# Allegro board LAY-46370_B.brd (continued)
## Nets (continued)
CSI1_DN2: J1.90 J12.B13 U33.1 U33.10(NC4)
CSI1_DN3: J1.96 J12.B16 U33.4 U33.7
CSI1_DP0: J1.74 J12.B3 U32.2 U32.9
CSI1_DP1: J1.80 J12.B6 U32.5 U32.6
CSI1_DP2: J1.92 J12.B14 U33.2 U33.9
CSI1_DP3: J1.98 J12.B17 U33.5 U33.6
CSI1_I2C_SCL: J12.B11 R162.1
CSI1_I2C_SDA: J12.B10 R160.1
CSI1_SYNC: J1.21 R28.1
CSI2_CKN: J2.16 J13.A2 U34.1 U34.10(NC4)
CSI2_CKP: J2.18 J13.A3 U34.2 U34.9
CSI2_DN0: J2.28 J13.B2 U35.1 U35.10(NC4)
CSI2_DN1: J2.22 J13.B5 U35.4 U35.7
CSI2_DN2: J2.10 J13.B13 U36.1 U36.10(NC4)
CSI2_DN3: J2.4 J13.B16 U36.4 U36.7
CSI2_DP0: J2.30 J13.B3 U35.2 U35.9
CSI2_DP1: J2.24 J13.B6 U35.5 U35.6
CSI2_DP2: J2.12 J13.B14 U36.2 U36.9
CSI2_DP3: J2.6 J13.B17 U36.5 U36.6
CSI2_I2C_SCL: J13.B11 R164.1
CSI2_I2C_SDA: J13.B10 R161.1
CSI2_MCLK: J13.B8 R26.1
CSI2_NRST: J13.B9 R303.1
CSI2_SYNC: J1.32 R25.1 R163.1
CSI_MCLK: J1.12 J12.B8 R26.2
CSI_NRST: J1.19 J12.B9 R303.2
CSI_PWDN: J2.71 J12.A11 R165.1
CSI_SYNC1: J12.A10 R28.2 R29.1
CSI_SYNC2: J13.A10 R25.2 R29.2
DCDC_5V: C16.1 C17.1 C41.1 C42.1 C61.2 C157.1 C256.2 C257.1 C258.1 C259.1 C260.1 C264.1 C270.1 C271.1 J25.1 J25.3 J25.5 J26.1 L16.2 Q8.1 Q8.2 Q8.3(S3) R254.1 R261.1 R267.1 R309.1 R310.1 TP67.1(PIN1) U14.D2 U14.D3 U14.E2 U14.E3 U14.F2 U14.F3 U14.G2 U14.G3 U22.A1 U22.A2(VIN2) U63.5(VOUT) U64.8 U64.11(VIN2) U71.3
DCDC_5V_CN: C158.1 C170.1 C171.1 R1.1 R179.1 R180.1 R185.2 TP125.1(TP) U48.8(VCCB) U71.2(OUT)
DEBUG_ACCESS: TP18.1(PIN1) U11.9
DEBUG_ACCESS1: TP27.1(PIN1) U17.9
DSI_BL_PWM: J1.23 R305.2
DSI_CKN: J1.83 J14.A2 U38.1 U38.10(NC4)
DSI_CKP: J1.85 J14.A3 U38.2 U38.9
DSI_DN0: J1.71 J14.B2 U37.1 U37.10(NC4)
DSI_DN1: J1.77 J14.B5 U37.4 U37.7
DSI_DN2: J1.89 J14.B13 U39.1 U39.10(NC4)
DSI_DN3: J1.95 J14.B16 U39.4 U39.7
DSI_DP0: J1.73 J14.B3 U37.2 U37.9
DSI_DP1: J1.79 J14.B6 U37.5 U37.6
DSI_DP2: J1.91 J14.B14 U39.2 U39.9
DSI_DP3: J1.97 J14.B17 U39.5 U39.6
DSI_EN: J1.30 J14.A11
DSI_NINT: J14.B9 R304.1
DSI_PWM: J14.B8 R305.1
DSI_TS_NINT: J1.28 R304.2
DSI_TS_SCL: J14.B11 R167.1
DSI_TS_SDA: J14.B10 R166.1
EARC_N_HPD: C162.1 J4.53 TP88.1(PIN1)
EARC_P_UTIL: C161.1 J4.55 TP87.1(PIN1)
ECSPI2_MISO: J4.37 U55.4
ECSPI2_MISO_3V3: J21.21 U55.8
ECSPI2_MOSI: J4.35 U55.3
ECSPI2_MOSI_3V3: J21.19 U55.9
ECSPI2_SCLK: J4.31 U55.5
ECSPI2_SCLK_3V3: J21.23 U55.7
ECSPI2_SS0: J4.33 U55.2
ECSPI2_SS0_3V3: J21.24 U55.10
EN_SNK1: Q2.3 R64.2 R65.1 U14.F1
EN_SRC1: R55.2 U14.G1
ENET1_EVENT_IN: R317.2 TP42.1(TP)
ENET1_EVENT_OUT: R318.2 TP56.1(TP)
ENET1_MDC: J3.86 R110.2
ENET1_MDIO: J3.88 R100.1 R111.2
ENET1_NINT: R114.1 U4.12 U26.31
ENET1_NRST: R113.1 U4.14 U26.12
ENET1_RD0: J3.92 R105.2
ENET1_RD1: J3.94 R103.2
ENET1_RD2: J3.96 R102.2
ENET1_RD3: J3.98 R106.2
ENET1_RX_CTL: J3.95 R107.2
ENET1_RXC: C99.1 J3.73 R108.2
ENET1_RXC/PHYAD1: R108.1 R119.1 R439.2 U26.27
ENET1_RXCTL/PHYAD2: R107.1 R126.1 U26.26
ENET1_RXD0/RXDLY: R105.1 R118.2 R125.1 U26.25
ENET1_RXD1/TXDLY: R103.1 R117.2 R124.1 U26.24
ENET1_RXD2/PLLOFF: R102.1 R120.2 R128.1 U26.23
ENET1_RXD3/PHYAD0: R106.1 R127.2 R438.1 U26.22
ENET1_TD0: J3.75 U26.18
ENET1_TD1: J3.77 U26.17
ENET1_TD2: J3.81 U26.16
ENET1_TD3: J3.83 U26.15
ENET1_TX_CTL: J3.85 U26.19
ENET1_TXC: J3.87 U26.20
ENET_MDC: J4.52 R79.2 R424.2
ENET_MDIO: J4.54 R80.2 R85.1 R425.2
ENET_NINT: R84.1 U4.13 U23.31
ENET_NRST: R83.1 U4.15 U23.12
ENET_RD0: J4.82 R73.2
ENET_RD1: J4.84 R72.2
ENET_RD2: J4.86 R71.2
ENET_RD3: J4.88 R75.2
ENET_RX_CTL: J4.72 R76.2
ENET_RXC: C81.1 J4.74 R77.2
ENET_TD0: J4.62 U23.18
ENET_TD1: J4.64 U23.17
ENET_TD2: J4.66 U23.16
ENET_TD3: J4.68 U23.15
ENET_TX_CTL: J4.56 U23.19
ENET_TXC: J4.58 U23.20
ETH1_1GB_LINK/ACTIVE: J9.11 R109.1
ETH1_10M_100M_LINK/ACTIVE: J9.13 R104.1
ETH1_AVDD1V0: C84.1 C85.1 C86.1 C339.1 L7.2 U26.3 U26.8 U26.38
ETH1_AVDD3V3: C87.1 C88.1 L6.2 U26.11 U26.40
ETH1_CLK125_OUT: TP35.1(PIN1) U26.35
ETH1_DVDD1V0: C14.1 C93.1 L8.2 U26.21
ETH1_DVDD3V3: C89.1 C90.1 L5.2 R115.1 R116.1 U26.29
ETH1_LED0/CFG_EXT: R115.2 R121.1 U26.32
ETH1_LED1/CFGLDO0: C100.1 J9.14 R123.1 U26.33
ETH1_LED2/CFGLDO1: C101.1 J9.12 R116.2 R122.1 U26.34
ETH1_MDC: R110.1 R424.1 U26.13
ETH1_MDIO: R111.1 R425.1 U26.14
ETH1_TRX0_N: J9.3 U26.2 U28.2 U28.9
ETH1_TRX0_P: J9.2 U26.1 U28.1 U28.10(NC4)
ETH1_TRX1_N: J9.5 U26.5 U28.5 U28.6
ETH1_TRX1_P: J9.4 U26.4 U28.4 U28.7
ETH1_TRX2_N: J9.7 U26.7 U27.2 U27.9
ETH1_TRX2_P: J9.6 U26.6 U27.1 U27.10(NC4)
ETH1_TRX3_N: J9.9(TRD4-) U26.10 U27.5 U27.6
ETH1_TRX3_P: J9.8 U26.9 U27.4 U27.7
ETH1_VDD1V0: C95.1 C96.1 L7.1 L8.1 U26.30
ETH1_VDDIO: C91.1 C92.1 R100.2 R101.2 R117.1 R118.1 R120.1 R127.1 R439.1 TP34.1(TP) U26.28
ETH1_XTALI: C97.1 U26.36 Y2.1
ETH1_XTALO: C98.1 U26.37(XTAL_OUT/ EXT_CLK) Y2.3
ETH_AVDD1V0: C65.1 C66.1 C67.1 C333.1 L3.2 U23.3 U23.8 U23.38
ETH_AVDD3V3: C68.1 C69.1 L2.2 U23.11 U23.40
ETH_CLK125_OUT: TP33.1(PIN1) U23.35
ETH_CT: C75.1 J8.1
ETH_CT1: C94.1 J9.1
ETH_DVDD1V0: C74.1 C334.1 L4.2 U23.21
ETH_DVDD3V3: C70.1 C71.1 L1.2 R86.1 R87.1 U23.29
ETH_TRX0_N: J8.3 U23.2 U25.2 U25.9
ETH_TRX0_P: J8.2 U23.1 U25.1 U25.10(NC4)
ETH_TRX1_N: J8.5 U23.5 U25.5 U25.6
ETH_TRX1_P: J8.4 U23.4 U25.4 U25.7
ETH_TRX2_N: J8.7 U23.7 U24.2 U24.9
ETH_TRX2_P: J8.6 U23.6 U24.1 U24.10(NC4)
ETH_TRX3_N: J8.9(TRD4-) U23.10 U24.5 U24.6
ETH_TRX3_P: J8.8 U23.9 U24.4 U24.7
ETH_VDD1V0: C76.1 C77.1 L3.1 L4.1 U23.30
ETH_VDDIO: C72.1 C73.1 R70.2 R85.2 R88.1 R89.1 R90.1 R91.1 TP32.1(TP) U23.28
ETH_XTALI: C79.1 U23.36 Y1.1
ETH_XTALO: C80.1 U23.37(XTAL_OUT/ EXT_CLK) Y1.3
EX_POR_B: R407.2 U1.24 U2.4(Y)
EXP_P0_7: J21.22 R142.2 U1.8
EXP_P1_0: J21.12 U1.10
EXP_P1_1: J21.13 U1.11
EXP_P1_2: J21.15 U1.12
EXP_P1_3: J21.16 U1.13
EXP_P1_4: J21.18(B9) U1.14
EXP_P1_5: J21.29 U1.15
EXP_P1_6: J21.31 U1.16
EXP_P1_7: J21.33 U1.17
EXT_3V3_PG: TP71.1(TP) U64.7
EXT_PWREN1: R271.1 U1.1
EXT_PWREN2: R281.1 R450.1 U1.2
FAN_5V: C348.1 J27.1 Q16.3
FAN_EN: R456.1 U1.5
FRS_EN: TP97.1(PIN1) U11.1
FRS_EN1: U14.B6 U17.1
FT_BOOT_MODE0: R386.2 U20.1
FT_BOOT_MODE1: R387.2 U20.4
FT_BOOT_MODE2: R388.2 U20.8
FT_BOOT_MODE3: R389.2 U20.11
FT_EECS: R240.2 U60.63
FT_EEDATA: R236.2 U60.61
FT_GPIO1: J25.25 U60.30
FT_GPIO2: J25.27 U60.32
FT_GPIO3: J25.31 U60.33
FT_GPIO4: J25.33 U60.34
FT_IO_01: J25.14 R390.2
FT_IO_02: J25.16 R391.2
FT_IO_03: J25.18 R392.2
FT_IO_04: J25.22 R393.2
FT_IO_05: J25.24 R395.2
FT_IO_06: J25.26 R396.2
FT_IO_07: J25.28 R397.2
FT_IO_08: J25.32 R398.2
FT_IO_09: J25.34 R399.2
FT_IO_10: J25.36 R400.2
FT_IO_11: J25.38 R401.2
FT_IO_NINT: R449.1 U60.29
FT_IO_NRST: J25.37 R412.1 U60.23
FT_IOEXP_SCL: R363.2 U70.19
FT_IOEXP_SDA: R364.2 U70.20
FT_ONOFF_B: R382.1 U60.24
FT_OSCI: C252.1 U60.2 X1.1
FT_OSCO: C253.1 U60.3 X1.3
FT_PWREN: TP93.1(PIN1) U60.60
FT_REMOTE_SEL: R394.2 R409.2 TP134.1(PIN1) U67.2
FT_RESET_B: J25.35 U60.21
FT_SCL: J25.21 R333.2 R363.1 R441.1 TP130.1(TP) U60.26
FT_SDA: J25.23 R334.2 R364.1 R442.1 TP129.1(TP) U60.27 U60.28
FT_SUSPEND_B: R408.1 TP96.1(PIN1) U60.36
FT_SYS_NRST: TP133.1(PIN1) U60.22 U66.2
FT_USB_DN: R327.1 U62.C2
FT_USB_DP: R328.1 U62.C1
FTA_TCK: U7.2 U60.16
FTA_TDI: U7.3 U60.17
FTA_TDO: U7.5 U60.18
FTA_TMS: U7.4 U60.19
FTDIC_RX: D17.C(CATHODE) U60.39 U61.15
FTDIC_TX: D16.C(CATHODE) U60.38 U61.13
FTDID_RX: D21.C(CATHODE) U60.52 U61.14
FTDID_TX: D20.C(CATHODE) U60.48 U61.12
GPIO1_IO00: J1.25 R315.1
GPIO1_IO12: J1.20 R308.1
HDMI_5V_CN: D10.1 J17.18 R1.2
HDMI_CEC: D32.A J4.49 Q5.2(SOURCE) R186.2
HDMI_CEC_CN: D13.1 D32.C(CATHODE) J17.13 Q5.3 R174.2
HDMI_CLKN_CN: J17.12 U46.A4
HDMI_CLKP_CN: J17.10 U46.A3
HDMI_DDC_SCL: J4.41 R177.2 R181.1 TP89.1(TP)
HDMI_DDC_SCL_CN: D12.1 J17.15 R179.2 U48.7
HDMI_DDC_SDA: J4.43 R178.2 R183.1 TP90.1(TP)
HDMI_DDC_SDA_CN: D11.1 J17.16 R180.2 U48.6
HDMI_HPD: J4.47 U79.4(Y)
HDMI_HPD/EARC-: C162.2 R175.2 TP95.1(PIN1) U30.C2
HDMI_HPD_5V: R175.1 R176.1 U79.2
HDMI_HPD_CN: J17.19 U30.A2
HDMI_TXCN: J4.59 U46.C4
HDMI_TXCP: J4.61 U46.C3
HDMI_TXN0: J4.65 U46.C2
HDMI_TXN0_CN: J17.9 U46.A2
HDMI_TXN1: J4.71 U47.C4
HDMI_TXN1_CN: J17.6 U47.A4
HDMI_TXN2: J4.77 U47.C2
HDMI_TXN2_CN: J17.3 U47.A2
HDMI_TXP0: J4.67 U46.C1
HDMI_TXP0_CN: J17.7 U46.A1
HDMI_TXP1: J4.73 U47.C3
HDMI_TXP1_CN: J17.4 U47.A3
HDMI_TXP2: J4.79 U47.C1
HDMI_TXP2_CN: J17.1 U47.A1
HDMI_UTILITY/EARC+: C161.2 TP94.1(PIN1) U30.C1
HDMI_UTILITY_CN: J17.14(UTILITY) U30.A1
HP_J_D: J18.5 R187.2 R189.2 TVS5.2(A2)
HP_J_L: C176.2 J18.4 L11.2 TVS4.2(A2)
HP_J_MIC: C193.1 J18.1 L13.2 TVS3.2(A2)
HP_J_R: C179.1 J18.3 L12.2 TVS6.2(A2)
HP_JD: R189.1 U50.7
HP_L: C177.1 U50.31
HP_MIC1N: C181.2 C183.1 U50.4
HP_MIC1P: C191.1 C192.1 U50.2
HP_MIC_P: C191.2 L13.1 R201.2
HP_R: C178.1 U50.29
HPL: C177.2 L11.1 R190.2
HPR: C178.2 L12.1 R196.1
I2C2_SCL: J3.55 R7.2 R153.2 R162.2 R167.2 R172.2 TP5.1(TP) U5.2
I2C2_SCL_3V3: R11.2 R58.1 R61.1 R133.1 U5.10
I2C2_SDA: J3.57 R8.2 R152.2 R160.2 R166.2 R170.2 TP6.1(TP) U5.3
I2C2_SDA_3V3: R12.2 R59.1 R62.1 R134.1 U5.9
I2C3_SCL: J3.61 R9.2 R164.2 R173.2 R198.1 R306.1 TP7.1(TP) U5.4
I2C3_SCL_3V3: J21.5 R13.2 R291.1 U5.8
I2C3_SDA: J3.63 R10.2 R161.2 R171.2 R197.1 R307.1 TP8.1(TP) U5.5
I2C3_SDA_3V3: J21.3 R14.2 R292.1 U5.7
I2C4_SCL: J3.65 R16.2 U6.2
I2C4_SDA: J3.67 R17.2 U6.3
I2C5_SCL: R18.2 TP9.1(TP) U6.4 U52.11
I2C5_SCL_3V3: R22.2 R221.1 U6.8
I2C5_SDA: R19.2 TP10.1(TP) U6.5 U52.8
I2C5_SDA_3V3: R23.2 R222.1 U6.7
ILIM_5V_VBUS: TP20.1(PIN1) U11.6
ILIM_5V_VBUS1: TP29.1(PIN1) U17.6
IOEXP_NINT: R308.2 U1.22
IOEXP_SCL: R306.2 U1.19
IOEXP_SDA: R307.2 U1.20
JTAG_MOD: J1.66 R313.1 TP122.1(PIN1)
JTAG_RESET: D23.C D26.C J24.10(B5) R245.2
JTAG_TCK: J1.68 U8.2
JTAG_TDI: J1.64 U8.5
JTAG_TDO: J1.62 U8.10
JTAG_TMS: J1.60 U8.7
LD1_I2C_SCL: R61.2 U14.B1
LD1_I2C_SDA: R62.2 U14.C1
LD1_NINT: R60.2 R63.2 U14.D1
LED0/CFG_EXT: R86.2 R92.1 U23.32
LED1/CFGLDO0: C82.1 J8.14 R94.1 U23.33
LED2/CFGLDO1: C83.1 J8.12 R87.2 R93.1 U23.34
LVDS0_CLK_N: J2.47 J15.A2 U40.1 U40.10(NC4)
LVDS0_CLK_P: J2.45 J15.A3 U40.2 U40.9
LVDS0_TS_SCL: J15.B11 R172.1
LVDS0_TS_SDA: J15.B10 R170.1
LVDS0_TX0_N: J2.35 J15.B2 U41.1 U41.10(NC4)
LVDS0_TX0_P: J2.33 J15.B3 U41.2 U41.9
LVDS0_TX1_N: J2.41 J15.B5 U41.4 U41.7
LVDS0_TX1_P: J2.39 J15.B6 U41.5 U41.6
LVDS0_TX2_N: J2.53 J15.B13 U42.1 U42.10(NC4)
LVDS0_TX2_P: J2.51 J15.B14 U42.2 U42.9
LVDS0_TX3_N: J2.59 J15.B16 U42.4 U42.7
LVDS0_TX3_P: J2.57 J15.B17 U42.5 U42.6
LVDS1_CLK_N: J2.17 J16.A2 U43.1 U43.10(NC4)
LVDS1_CLK_P: J2.15 J16.A3 U43.2 U43.9
LVDS1_TS_SCL: J16.B11 R173.1
LVDS1_TS_SDA: J16.B10 R171.1
LVDS1_TX0_N: J2.5 J16.B2 U44.1 U44.10(NC4)
LVDS1_TX0_P: J2.3 J16.B3 U44.2 U44.9
LVDS1_TX1_N: J2.11 J16.B5 U44.4 U44.7
LVDS1_TX1_P: J2.9 J16.B6 U44.5 U44.6
LVDS1_TX2_N: J2.23 J16.B13 U45.1 U45.10(NC4)
LVDS1_TX2_P: J2.21 J16.B14 U45.2 U45.9
LVDS1_TX3_N: J2.29 J16.B16 U45.4 U45.7
LVDS1_TX3_P: J2.27 J16.B17 U45.5 U45.6
LVDS_BL_PWM: J1.22 J15.B8 R168.2
LVDS_EN: J1.26 J15.A11 J16.A11
LVDS_TS_NINT: J1.18 J15.B9 R169.2
LVL_SHF_TCK: U7.10 U8.1
LVL_SHF_TDI: U7.9 U8.4
LVL_SHF_TDO: U7.7 U8.11
LVL_SHF_TMS: U7.8(YB3) U8.8
M2_BT_WAKE: D6.C J10.20 R149.2
M2_BT_WAKE_HOST: D6.A J2.95
M2_DIS1: J10.56 R32.1
M2_DIS2: J10.54(W\_\D\I\S\A\B\L\E\2\) R142.1 TP39.1(PIN1)
M2_I2C_SCL: J10.60 R153.1
M2_I2C_SDA: J10.58 R152.1
M2_LED1#: D30.C(CATHODE) J10.6
M2_LED2#: D31.C(CATHODE) J10.16
M2_PCM_CLK: J4.11 J10.8
M2_PCM_IN: J4.17 J10.12
M2_PCM_OUT: J4.15 J10.14
M2_PCM_SYNC: J4.13 J10.10
M2_PERST: J10.52 R31.1
M2_SD_CLK: J2.75 J10.9
M2_SD_CMD: J2.77 J10.11
M2_SD_DATA0: J2.81 J10.13
M2_SD_DATA1: J2.83 J10.15
M2_SD_DATA2: J2.85 J10.17
M2_SD_DATA3: J2.87 J10.19
M2_SD_NRST: J2.73 J10.23
M2_SD_WAKE_HOST: J2.97 J10.21
M2_UART_CTS: J3.56 R372.2 TP119.1(TP)
M2_UART_RTS: J3.58 R371.2 TP118.1(TP)
M2_UART_RXD: J3.54 R369.2 TP116.1(TP)
M2_UART_TXD: J3.52 R370.2 TP117.1(TP)
M2_USB_DN: J10.5 R301.2 TP38.1(PIN1)
M2_USB_DP: J10.3 R300.2 TP37.1(PIN1)
MICBIAS: C174.1 R199.1 U50.1
NAND_DQS: J2.72 U3.8
NX5P_EN: R302.2 U22.B4
NX5P_FLT#: R448.2 U22.A4
NX5P_FRS: R68.2 U22.C4
NX5P_ILIM: R67.2 U22.A3
NX20P_ACK: R43.1 TP13.1(PIN1) U9.A2
NX20P_EN: C164.1 Q1.3 R42.2 U9.A3(\\E\N)
NX20P_OVLO: R44.1 U9.B3
ONOFF: J2.74 R381.2 SW1.3 SW1.4(B2) TP120.1(PIN1)
P0_0: R386.1 U70.1
P0_1: R387.1 U70.2
P0_2: R388.1 U70.3
P0_3: R389.1 U70.4
P0_4: R390.1 U70.5
P0_5: R391.1 U70.6
P0_6: R392.1 U70.7
P0_7: R393.1 U70.8
P1_0: R394.1 U70.10
P1_1: R395.1 R415.2 U70.11
P1_2: R396.1 R416.2 U70.12
P1_3: R397.1 R417.2 U70.13
P1_4: R398.1 R418.2 U70.14
P1_5: R399.1 R419.2 U70.15
P1_6: R400.1 R420.2 U70.16
P1_7: R401.1 R421.2 U70.17
PCIE_CLKN: J1.53 R132.2 R136.1
PCIE_CLKP: J1.55 R131.2 R135.1
PCIE_DIG1: C102.1 C103.1 C349.1 R129.2 R130.2 U29.7 U81.6
PCIE_NCLKREQ_3V3: J10.53 R20.2 R144.1 TP98.1(PIN1) U6.10 U81.2
PCIE_NDIS_3V3: R32.2 R33.1 TP101.1(TP) U3.21
PCIE_NRST_3V3: R31.2 TP100.1(TP) U3.20
PCIE_NWAKE_3V3: J10.55 R21.2 U6.9
PCIE_REQ: R139.1 R140.1 R144.2 U81.4(Y)
PCIE_RXN: J1.59 J10.43
PCIE_RXP: J1.61 J10.41
PCIE_TXN: C121.1 J1.65
PCIE_TXP: C120.1 J1.67
PD1_I2C_SCL: R58.2 U17.8
PD1_I2C_SDA: R59.2 U17.7
PD_EN_SNK: Q2.1 R2.1 U11.2
PD_EN_SNK1: R64.1 U17.2
PD_EN_SRC: TP17.1(PIN1) U11.16
PD_EN_SRC1: R55.1 U17.16
PD_I2C_SCL: R291.2 U11.8
PD_I2C_SDA: R292.2 U11.7
PDM/CAN2_SEL: R445.1 U1.4 U54.10
PDM_CLK: J21.40 U58.10
PDM_STREAM_0: J21.38 U57.10
PDM_STREAM_1: J21.37 U57.9
PDM_STREAM_2: J21.36 U57.8
PDM_STREAM_3: J21.35 U57.7
PER_12V: C146.1 C151.1 C280.1 C281.1 C282.1 J15.A8 J15.A9 J16.A8 J16.A9 L18.2 R276.1 TP105.1(PIN1)
PER_12V_PG: R282.2 TP81.1(TP) U49.6
PMIC_32K_OUT: J3.41 R314.1
PMIC_ON_REQ: J2.78 R265.1
PMIC_SCLH: J3.51 TP54.1(PIN1)
PMIC_SCLL: J3.45 TP52.1(PIN1)
PMIC_SDAH: J3.53 TP55.1(PIN1)
PMIC_SDAL: J3.47 TP53.1(PIN1)
POR_B: D26.A J2.76 R238.1 R407.1 U2.2
POR_B_INVERT: R431.2 R435.1 U78.4(Y)
PWM4_3V3: J21.32 U58.7
PWR_MEAS_IO1: J25.15 U1.6
PWR_MEAS_IO2: J25.17 U1.7
REF_CLK_32K: R314.2 R315.2 U3.5
REF_CLK_32K_3V3: R30.2 U3.19
REF_CLKN_CN: J10.49 R136.2 R138.2
REF_CLKP_CN: J10.47 R135.2 R137.2
REG_FT_1V8: C294.1 C295.1 L24.2 U60.49(VREGOUT)
REMOTE_SEL: Q12.1 R39.2 R351.1 R458.1 U8.15 U20.15
REMOTE_SEL_B: Q12.3 R385.2 U7.12
RXC/PHYAD1: R77.1 R98.1 U23.27
RXCTL/PHYAD2: R76.1 R97.1 U23.26
RXD0/RXDLY: R73.1 R89.2 R96.1 U23.25
RXD1/TXDLY: R72.1 R88.2 R95.1 U23.24
RXD2/PLLOFF: R71.1 U23.23
RXD2_PLLOFF: R91.2 R99.1
RXD3/PHYAD0: R75.1 R90.2 U23.22
S_TXN1: C48.2 U18.7
S_TXN2: C53.2 U18.6
S_TXP1: C50.2 U18.8
S_TXP2: C52.2 U18.5
SAI1_RXC: J3.78 R318.1
SAI1_RXD0: J3.82 U4.7
SAI1_RXD1: J3.84 U4.9
SAI1_RXFS: J3.76 R317.1
SAI2_MCLK: J4.18 U3.10
SAI2_RXC: J4.14 U4.6
SAI2_RXFS: J4.12 U4.8
SAI3_MCLK: J4.22 R195.1
SAI3_RXD: J4.28 R194.1
SAI3_TXC: J4.21 R191.1
SAI3_TXD: J4.25 R193.1
SAI3_TXFS: J4.23 R192.1
SAI5_RX3: J4.7 U54.1
SAI5_RXC: J4.4 R297.1 TP86.1(TP)
SAI5_RXD0: J4.1 R293.1 TP82.1(TP)
SAI5_RXD1: J4.3 R294.1 TP83.1(TP)
SAI5_RXD2: J4.5 R295.1 TP84.1(TP)
SAI5_RXD3: R296.1 TP85.1(TP) U54.2
SAI5_RXFS: J4.2 U58.5
SD1_DATA4: J2.91 U3.3
SD1_DATA5: J2.93 R41.2 U3.4
SD2_CLK: J4.96 R155.1
SD2_CMD: J4.98 R154.1
SD2_DATA0: J4.91 R156.1
SD2_DATA1: J4.93 R157.1
SD2_DATA2: J4.95 R158.1
SD2_DATA3: J4.97 R159.1
SD2_NCD: J4.94 J11.9 TP40.1(PIN1) TVS1.2(A2)
SD2_RESET_B: J4.87 TP62.1(PIN1)
SPDIF_EXT_CLK: J4.36 U3.9
SPDIF_RX: J4.34 TP12.1(TP) U52.4
SPDIF_TX: J4.32 TP11.1(TP) U52.1
SPK_LN: R208.1 U50.23
SPK_LP: R206.1 U50.25
SPK_RN: R203.1 U50.19
SPK_RP: R202.1 U50.22
SPKOUTLN: C199.2 C201.1 CON1.4 R208.2
SPKOUTLP: C198.2 C199.1 CON1.3 R206.2
SPKOUTRN: C195.2 C196.1 CON1.2 R203.2
SPKOUTRP: C194.2 C195.1 CON1.1 R202.2
SS_RXN1: U18.1 U19.C2
SS_RXN2: U18.16 U19.C4
SS_RXP1: U18.2 U19.C1
SS_RXP2: U18.15 U19.C3
SS_TXN1: C48.1 U16.C3
SS_TXN2: C53.1 U16.C1
SS_TXP1: C50.1 U16.C4
SS_TXP2: C52.1 U16.C2
SSRXN1: J6.B10 U19.A2
SSRXN2: J6.A10 U19.A4
SSRXP1: J6.B11 U19.A1
SSRXP2: J6.A11 U19.A3
SSTXN1: J6.A3 U16.A3
SSTXN2: J6.B3 U16.A1
SSTXP1: J6.A2 U16.A4
SSTXP2: J6.B2 U16.A2
ST_FT_USB_DN: R327.2 U60.7
ST_FT_USB_DP: R328.2 U60.8
SUSCLK_3V3: J10.50 R30.1 TP99.1(TP)
SW_BOOT_MODE0: R287.1 SW4.4 U20.16
SW_BOOT_MODE1: R288.1 SW4.3 U20.3
SW_BOOT_MODE2: R289.1 SW4.2 U20.9
SW_BOOT_MODE3: R290.1 SW4.1 U20.12
SYS_NRST: D23.A J3.43 R406.2 R436.2 TP121.1(PIN1)
TCPC_NINT: J3.91 TP22.1(TP) U11.10
TCPC_NINT1: J3.93 TP31.1(TP) U17.10
TYPEC_EN_B: R40.1 U18.3(XSD)
UART2_RXD: J3.64 R232.1 TP58.1(TP)
UART2_TXD: J3.62 R230.1 TP57.1(TP)
UART3_CTS: J4.42 U56.4
UART3_CTS_3V3: J21.7 U56.8
UART3_RTS: J4.44 U56.5
UART3_RTS_3V3: J21.11 U56.7
UART3_RXD: J4.48 U56.3
UART3_RXD_3V3: J21.10 U56.9
UART3_TXD: J4.46 U56.2
UART3_TXD_3V3: J21.8 U56.10
UART4_RXD: J3.68 R233.1 TP61.1(TP)
UART4_TXD: J3.66 R231.1 TP60.1(TP)
USB1_CC1: TP28.1(PIN1) U15.A2 U17.13
USB1_CC1_CN: J6.A5 U15.A1
USB1_CC2: TP30.1(PIN1) U15.B2 U15.C1 U15.C2 U17.14
USB1_CC2_CN: J6.B5 U15.B1
USB1_DN: J1.36 U75.C1
USB1_DN_CN: J6.A7 J6.B7 U75.A1
USB1_DNU(USB1_ID): TP45.1(PIN1)
USB1_DP: J1.38 U75.C2
USB1_DP_CN: J6.A6 J6.B6 U75.A2
USB1_OTG_VBUS: F2.1 J6.A4 J6.A9 J6.B4(VBUS4) J6.B9
USB1_OTG_VBUS_F: C36.1 D4.A F2.2 R5.1 R47.1 U14.C2 U14.C3 U14.C4 U14.C5 U14.D4 U14.D5 U14.E4 U14.E5 U14.F4 U14.F5 U14.G4 U14.G5 U17.15
USB1_RXN: J1.29 U18.14
USB1_RXP: J1.31 U18.13
USB1_SBU1: J6.A8 TP24.1(PIN1)
USB1_SBU2: J6.B8 TP25.1(PIN1)
USB1_SS_SEL: J3.97 R38.1 U18.12
USB1_TXN: J1.35 U18.9
USB1_TXP: J1.37 U18.10
USB1_TYPEC_EN_B: J4.92 R40.2
USB1_VBUS_3V3: J1.44 R48.2 U12.1
USB1_VBUS_IN: C43.2 R53.1 R54.1 TP110.1(PIN1) U14.C6 U14.D6 U14.E6 U14.F6 U14.G6
USB2_DN: J1.54 R299.2 R301.1
USB2_DNU(USB2_ID): TP46.1(PIN1)
USB2_DP: J1.56 R298.2 R300.1
USB2_H_DN: R299.1 U77.C1
USB2_H_DP: R298.1 U77.C2
USB2_H_TXN: C60.1 U21.C2
USB2_H_TXP: C59.1 U21.C1
USB2_HOST_VBUS: C62.1 D5.C J7.1(VBUS) TP103.1(TP) U22.C2 U22.D1 U22.D2
USB2_PWR_EN: J1.16 R302.1
USB2_RXN: J1.41 U21.C4
USB2_RXP: J1.43 U21.C3
USB2_TXN: C60.2 J1.47
USB2_TXP: C59.2 J1.49
USB2_VBUS_3V3: J1.50 R66.2
USB_CC1: TP19.1(PIN1) U10.A2 U11.13
USB_CC1_CN: J5.A5 SW3.3
USB_CC1_ESD: SW3.2 U10.A1
USB_CC2: TP21.1(PIN1) U10.B2 U10.C1 U10.C2 U11.14
USB_CC2_CN: J5.B5 SW3.6(NO2)
USB_CC2_ESD: SW3.5 U10.B1
USB_DBG_DN: J23.2 U62.A2
USB_DBG_DP: J23.3 U62.A1
USB_HOST_DN: J7.2 U77.A1
USB_HOST_DP: J7.3 U77.A2
USB_HOST_RXN: J7.5 U21.A4
USB_HOST_RXP: J7.6 U21.A3
USB_HOST_TXN: J7.8 U21.A2
USB_HOST_TXP: J7.9 U21.A1
USB_LD_NFLT: R447.1 U11.11
USB_LD_NFLT1: R63.1 U17.11
USB_PWR_VBUS_F: C24.1 D2.A F1.2 R42.1 R453.1 U9.B2 U9.C2 U9.D2 U9.E1 U9.E2 U11.15
USB_SBU1: J5.A8 TP14.1(PIN1)
USB_SBU2: J5.B8 TP15.1(PIN1)
VEXP_3V3: C224.1 C229.1 C231.1 C233.1 C235.1 J21.1 J21.17 L25.2 U55.11(VCCB) U56.11(VCCB) U57.11(VCCB) U58.11(VCCB)
VEXP_5V: C226.1 J21.2 J21.4 L26.2
VEXT_3V3: C127.1 C128.1 C133.1 C134.1 C139.1 C140.1 C144.1 C149.1 C153.1 C155.1 C223.2 C272.1 C273.1 C274.1 C275.1 C276.2 C340.1 C342.1 J12.A13 J12.A14 J13.A13 J13.A14 J14.A13 J14.A14 J15.A13 J15.A14 J16.A13 J16.A14 J22.1 J22.2 L17.2 L25.1 Q14.1 Q14.2 Q14.3(S3) R36.1 R268.1 R451.1 TP70.1(PIN1) U64.2
VEXT_3V3_EN: R37.1 U3.16
VLDO1_3V3: C47.1 U14.A5(VLDO)
VLDO_3V3: C27.1 C35.1 C45.1 C46.1 TP23.1(TP) U10.A3(VSYS) U13.5(OUT) U14.A1 U15.A3(VSYS)
VPCIE_3V3: C112.1 C113.1 C114.1 C115.1 C116.1 C117.1 C118.1 C119.1 C341.2 J10.2 J10.4 J10.72 J10.74 Q14.5 R35.1 R149.1 R373.2 R374.2 TP104.1(TP)
VSD_3V3: C123.1 C124.1 J3.42 J3.44 J3.46 J11.4 TP41.1(PIN1) TVS2.2(A2)
VSYS_5V: J3.1 J3.2 J3.3 J3.4 J3.5 J3.6 J3.7 J3.8 J3.9 J3.10 J3.11 J3.12 J26.2 R309.2 R310.2
VTREF: J24.1 R246.2
WDOG_B: J1.10 R437.2
N98831920: J11.5 R155.2
N101118683: J11.8 R157.2
N101118691: J11.7 R156.2
N101118780: J11.3 R154.2
N101118796: J11.1 R158.2
N101783582: J11.2 R159.2
N101995244: C107.1 C108.1 C109.1 L10.2 U29.11 U29.20
N101995252: C111.1 U29.2(X2) Y3.3
N101995256: C110.1 U29.1 Y3.1
N101995353: C104.1 C105.1 C106.1 L9.1 U29.3 U29.16
N101995404: R131.1 U29.13
N101995406: TP36.1(PIN1) U29.4
N101995408: R132.1 U29.14
N101995436: R137.1 U29.17
N101995453: R138.1 U29.18
N101995643: R140.2 U29.19
N101995645: R139.2 U29.12
N101995688: R141.2 U29.23
N103620610: C265.1 D24.C(CATHODE) R24.1 R252.2 TVS8.2(A2)
N103620792: C254.2 L16.1 R253.1 U63.7
N103620806: R251.1 U63.8
N103620818: C254.1 R251.2
N103621273: R254.2 R256.2 R260.1 U63.11
N103621294: R258.2 R259.1 U63.6
N104279466: R133.2 U29.8
N104279469: R134.2 U29.9
N104764716: R147.2 R148.2 U29.5
N105095140: C120.2 J10.35
N105095143: C121.2 J10.37
N106947509: C261.2 C264.2 Q8.4 R261.2 R263.1
N106947511: Q10.3 R263.2
N106947532: C269.1 Q10.1 R264.2 R265.2 R266.1
N107574242: J22.3 J22.4 R221.2
N107574341: J22.5 J22.6 R222.2
N107626870: C277.1 R37.2 R269.2 R271.2 R272.1 U64.5
N107626960: C272.2 R268.2 R273.1 U64.3
N107627021: R267.2 U64.6
N107627023: L17.1 U64.1 U64.9
N107627186: C276.1 U64.4
N107870832: C256.1 R253.2 R256.1
N107900649: R24.2 U63.12
N108223184: C240.1 U59.4
N108629575: J12.A8 J12.A9 TP43.1(PIN1)
N108650969: C43.1 U14.A6
N108650998: C44.1 U14.A3
N108651072: R56.2 U14.A2
N108651079: R57.2 U14.E1
N108651264: TP26.1(PIN1) U15.C3
N108688907: C64.1 U22.D4
N108749685: R188.2 U50.15
N108749687: C175.1 U50.27(VMID)
N108749719: R192.2 U50.13
N108749740: R191.2 U50.12
N108749771: R194.2 U50.16
N108749815: R193.2 U50.14
N108749834: R195.2 U50.11
N108749893: TP51.1(PIN1) U50.30
N108750085: C182.1 R199.2 R200.1
N108750181: C183.2 R200.2 R201.1
N108752359: C197.2 Q6.1 R204.2 R205.1
N108752379: Q7.3 R205.2
N108752409: C200.1 Q7.1 R207.2 R209.1
N108779922: D5.A U22.B1 U22.B2 U22.C1
N108856282: R81.1 U23.39
N108894167: R79.1 U23.13
N108894170: R80.1 U23.14
N108934835: R112.1 U26.39
N108973788: F1.1 J5.A4 J5.A9 J5.B4(VBUS4) J5.B9
N108973950: TP16.1(PIN1) U10.C3
N108990768: R4.2 U3.2
N108992491: R15.2 U5.12
N108999488: C163.1 Q1.1 R2.2 R45.1
N109006824: C278.1 U49.10
N109006844: C278.2 L18.1 U49.9
N109007030: C280.2 R276.2 R280.1 U49.14
N109010135: R281.2 U49.4
N109011918: D25.A R270.2
N109066072: C207.1 R210.2 R211.2
N109088165: C215.1 R214.2 R215.2
N109209998: J13.A8 J13.A9 TP44.1(PIN1)
N109210079: J13.A11 R163.2 R165.2
N109239152: R181.2 U48.2
N109239179: R183.2 U48.3
N109242668: R185.1 U48.5
N109294186: J14.A8 J14.A9 TP47.1(PIN1)
N109296461: J14.A10 TP48.1(PIN1)
N109299410: J15.A10 TP49.1(PIN1)
N109302474: J16.B8 R168.1
N109302491: J16.B9 R169.1
N109302514: J16.A10 TP50.1(PIN1)
N109310681: R218.2 U53.1 U53.16
N109310959: R216.2 U53.4
N109310972: R217.2 U53.5
N109373964: R223.2 U55.12
N109397839: R224.2 U56.12
N109400332: R225.2 U57.12
N109402713: R226.2 U58.12
N109415208: R27.2 U6.12
N109503700: R293.2 U57.2
N109503714: R294.2 U57.3
N109503728: R295.2 U57.4
N109503742: R296.2 U57.5
N109503902: R297.2 U58.2
N109622186: R406.1 SW2.3 SW2.4(B2)
N109731195: R312.2 U4.4
N109731201: R322.2 U4.5
N109731216: R323.2 U4.1 U4.16
N109737134: C241.1 L21.2 U60.9
N109737207: C242.1 L22.2 U60.4
N109737719: C251.1 R329.2 U60.14
N109737725: R330.1 U60.6
N109773309: D20.A R242.1
N109773326: D21.A R241.1
N109773834: D16.A R235.1
N109773857: D17.A R237.1
N109792630: R347.1 U8.13
N109864993: D22.C R245.1
N109865112: J24.7 R247.1
N109865133: J24.9 R248.1
N109916641: R427.1 U20.13
N109928082: J10.34 R371.1
N109928083: J10.32 R370.1
N109928084: J10.36 R372.1
N109928085: J10.22 R369.1
N109928213: D30.A R373.1
N109928444: D31.A R374.1
N109980953: Q11.1 R382.2 R383.2
N109981204: Q11.3 R381.1
N109995760: C325.1 L23.1 U74.5(VOUT)
N109995782: C326.1 U74.4
N110028547: R408.2 R410.2 U67.1
N110029062: R39.1 U67.4(Y)
N110030307: R411.2 R412.2 U70.24
N110030899: R413.2 R449.2 U70.22
N110063389: J10.38 R422.1
N110063392: J10.40 R423.1
N110097895: C34.1 D2.C(CATHODE) D4.C(CATHODE) R50.1 U13.1
N110098002: R49.2 R50.2 U13.3
N110105894: R429.2 U61.4
N110105900: R430.2 U61.5
N110105915: R435.2 U61.1 U61.16
N110106386: R230.2 U61.6
N110106400: R231.2 U61.7
N110106414: R232.2 U61.8
N110106418: R233.2 U61.9
N110115246: R238.2 U78.2
N110122839: C332.2 U49.13
N110220095: R436.1 R437.1 U66.4(Y)
N110240993: C283.2 U49.11
N110241540: R278.1 U49.15
N110634243: R446.1 U49.7
N111139968: R283.1 SW4.8
N111139982: R284.1 SW4.7
N111139996: R285.1 SW4.6
N111140010: R286.1 SW4.5(B4)
N111151516: C340.2 C341.1 Q14.4 R451.2 R452.1
N111151562: Q13.3 Q15.1 R452.2
N111153330: C343.1 Q13.1 R33.2 R34.1 R36.2
N111155456: Q15.3 R35.2
N112037494: R46.2 R52.1 U12.4
N112037543: R47.2 R51.1 U12.3
N112068055: R441.2 U80.5
N112068081: R440.1 U80.1 U80.2 U80.3
N112068092: R442.2 U80.6
N112068114: R443.2 U80.7(WP)
N112246951: Q16.1 Q17.3 R455.2
N112247388: Q17.1 R456.2 R457.1
N112941127: R458.2 U66.1

Pads without a net: J1 1 2 3 4 5 6 42 48; J2 34 36 38 42 44 46 48 52 54 56 58 62 63 64 65 66 67 68 82; J3 48 71 72 74; J4 6 16 27 38 76 78 83 85; J5 A2 A3 A6 A7 A10 A11 B2 B3 B6 B7 B10 B11; J10 42 44 46 48 59 61 62 64 65 66 67 68 70 71 73; J18 6; J19 1 4 8 9; J20 1 4 8 9; J21 26 27 28; J23 4; J25 13; SW3 1 4; U2 5; U3 6 7 17 18; U10 D1 D2; U13 4; U15 D1 D2; U31 4 5 6 7; U34 4 5 6 7; U38 4 5 6 7; U40 4 5 6 7; U43 4 5 6 7; U49 1 5; U50 3 5 6; U54 4 5 7 8; U58 3 4 8 9; U60 40 41 43 44 45 46 53 54 55 57 58 59 62; U63 4; U66 5; U67 5; U78 1 5; U79 5; U81 5

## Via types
v1: diameter 0.457, hole 0.203, TOP to BOTTOM, 4573 vias

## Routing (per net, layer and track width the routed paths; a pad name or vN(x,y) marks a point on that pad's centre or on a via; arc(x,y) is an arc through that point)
5V_PG: length 2.4
  BOTTOM w0.254: TP69.1 46.45,65.54 U63.3
GND: length 489.2
  TOP w0.178: J4.9 116.66,63.81 v1(116.69,63.77)
  TOP w0.203: v1(75.52,111.45) 75.49,111.41 J1.24 ; v1(116.69,79.72) 116.61,79.81 J4.89 ; J2.14 v1(97.13,111.39) ; U47.B1 v1(154.74,137.56) ; v1(72.15,111.38) 72.29,111.25 J1.8 ; v1(182.62,56.48) 182.42,56.68 U57.6 ; 58.82,32.15 58.93,32.27 U14.A4 U14.B4 ; v1(42.85,13.3) 42.85,13.1 U15.D3 ; v1(41.84,13.33) 41.74,13.23 U15.B3 ; v1(46,28.21) 46.12,28.09 U17.5 ; J2.2 v1(94.73,111.39) ; v1(73.37,111.39) 73.49,111.27 J1.14 ; v1(72.09,106.81) 72.29,107.01 J1.7 ; J1.52 81.09,111.43 v1(81.08,111.44) ; J1.33 77.49,106.83 v1(77.45,106.8) ; v1(108.69,64.14) 108.62,64.07 J3.100 ; J1.81 87.09,106.81 v1(87.1,106.8) ; J2.19 v1(98.33,106.83) ; J1.82 87.09,111.39 v1(87.09,111.39) ; U4.10 118.13,33.83 v1(117.98,33.98) 117.73,33.73 U4.11 ; v1(114.6,111.36) 114.6,111.17 114.33,110.9 J2.100 ; J4.80 112.21,77.81 v1(112.13,77.73) ; J4.57 v1(116.69,73.4) ; J2.8 v1(95.93,111.39) ; v1(79.86,111.95) 79.99,111.82 79.99,111.16 79.89,111.06 J1.46 ; J1.39 v1(78.69,106.83) ; v1(25.9,13.3) 25.81,13.21 U10.B3 ; J3.49 98.62,59.53 v1(98.54,59.45) ; v1(160.88,137.53) 160.85,137.56 U30.B1 ; v1(188.68,30.41) 188.83,30.41 188.92,30.32 U50.20 ; J4.70 v1(112.13,75.81) ; v1(76.36,106.8) 76.36,106.81 76.29,106.87 J1.27 ; U5.6 v1(179.92,99.75) ; v1(98.56,64.16) 98.56,63.98 98.62,63.92 J3.50 ; J2.7 v1(95.93,106.83) ; v1(116.69,67.75) 116.63,67.81 J4.29 ; J4.50 112.18,71.81 112.15,71.77 v1(112.13,71.77) ; J4.81 v1(116.69,78.2) ; U10.D3 26.79,12.92 v1(27.12,12.92) ; J2.88 111.93,111.42 v1(111.7,111.65) ; v1(77.55,111.39) 77.49,111.33 J1.34 ; v1(102.66,64.1) 102.62,64.06 J3.70 ; v1(82.43,111.46) 82.29,111.32 J1.58 ; U77.B1 64.91,20.6 v1(64.85,20.66) ; J2.37 v1(101.93,106.83) ; v1(112.76,111.48) 112.76,111.36 112.73,111.33 J2.92 ; v1(182.48,92.16) 182.48,92.17 182.64,92.32 U56.6 ; v1(114.49,106.84) 114.33,106.99 J2.99 ; J2.69 108.33,106.85 v1(108.3,106.82) ; U61.11 11.02,36.27 v1(10.79,36.5) 10.97,36.67 U61.10 ; J2.43 v1(103.13,106.83) ; J2.96 113.53,111.28 v1(113.64,111.39) ; J25.40 34.36,64.24 v1(34.4,64.29) ; J2.61 v1(106.73,106.83) ; J4.63 v1(116.69,74.6) ; J2.55 v1(105.53,106.83) ; J4.20 v1(112.13,65.81) ; U62.B1 14.02,8.67 v1(13.99,8.69) ; J2.70 v1(108.33,111.39) ; J2.84 111.13,111.1 v1(110.68,111.55) 110.33,111.2 J2.80 ; U46.B1 v1(156.91,137.55) 156.9,137.56 U47.B2 ; J1.40 78.69,111.41 v1(78.64,111.46) ; v1(84.73,111.39) 84.69,111.34 J1.70 ; U14.B5 U14.B4 ; U14.B4 U14.B3 U14.B2 ; U55.6 v1(182.59,74.24) ; U16.B2 v1(45.43,12.43) ; v1(84.7,106.8) 84.69,106.81 J1.69 ; J1.94 v1(89.49,111.41) ; J2.25 v1(99.53,106.83) ; U75.B1 v1(43.84,12.43) ; v1(85.9,106.8) 85.89,106.81 J1.75 ; J2.40 v1(102.33,111.39) ; J2.1 v1(94.73,106.83) ; v1(89.5,106.8) 89.49,106.81 J1.93 ; U19.B1 v1(50.41,12.38) ; J4.40 v1(112.13,69.81) ; U50.28 v1(191.71,26.94) ; J4.99 116.64,81.81 v1(116.69,81.86) ; v1(49.01,15.54) 49.12,15.65 U18.11 ; J2.50 104.33,111.32 v1(104.47,111.45) ; U11.5 v1(33.44,19.64) ; J3.89 106.62,59.58 v1(106.56,59.51) ; J4.69 v1(116.69,75.81) ; J4.100 v1(112.87,82.29) ; J25.19 v1(30.36,59.56) ; J4.45 v1(116.69,71) ; J2.13 v1(97.13,106.83) ; J1.63 v1(83.49,106.83) ; J2.60 v1(106.33,111.39) ; v1(112.09,67.86) 112.14,67.86 112.19,67.81 J4.30 ; J4.51 v1(116.71,72.2) ; J1.51 v1(81.09,106.83) ; J2.49 v1(104.33,106.83) ; J1.87 88.29,106.81 v1(88.3,106.8) ; v1(74.14,106.83) 74.29,106.98 J1.17 ; J4.19 v1(116.69,65.81) ; J4.39 v1(116.69,69.81) ; J2.26 v1(99.53,111.39) ; U58.6 v1(182.45,47.95) ; J2.20 v1(98.33,111.39) ; J1.45 v1(79.89,106.83) ; U19.B2 v1(48.4,12.38) ; U53.10 133.6,38.14 133.4,37.94 v1(133.4,37.94) 133.59,37.74 U53.11 ; J25.20 v1(30.36,64.22) ; v1(102.63,59.54) 102.63,59.66 102.62,59.67 J3.69 ; J2.89 v1(112.33,106.83) ; J4.90 v1(112.13,79.81) ; J25.30 v1(32.36,64.22) ; v1(68.63,20.66) 68.59,20.61 U21.B1 ; U21.B2 66.62,20.61 v1(66.58,20.66) ; J1.88 v1(88.29,111.41) ; J3.59 v1(100.62,59.54) ; v1(90.7,106.8) 90.69,106.81 J1.99 ; J1.76 v1(85.89,111.43) ; J3.90 v1(106.62,64.29) ; J4.75 v1(116.69,77) ; J3.60 v1(100.62,64.1) ; J3.80 v1(104.62,64.14) ; J2.31 v1(100.73,106.83) ; J25.29 v1(32.36,59.67) ; v1(90.74,111.41) 90.69,111.35 J1.100 ; J4.10 v1(112.13,63.81) ; U16.B1 v1(47.4,12.43) ; J4.60 v1(112.11,73.81) ; J1.57 v1(82.29,106.83) ; U46.B2 v1(159.12,137.55) ; J3.79 v1(104.62,59.53)
  TOP w0.254: v1(108.7,59.49) 108.62,59.57 J3.99 ; v1(14.07,14.59) 13.77,14.89 U60.10 ; U36.8 v1(80.8,124.88) ; U35.8 v1(89.71,124.88) ; J2.79 110.33,106.88 v1(110.44,106.77) ; v1(17.73,21.82) 17.86,21.7 U60.25 ; v1(156.09,100.86) 156.31,101.09 C349.2 ; U27.3 v1(84.46,18.62) ; U79.1 163.9,131.18 C345.2 ; U33.8 v1(57.14,124.88) ; U24.8 v1(104.82,21.15) ; v1(10.3,26.08) 10.13,26.08 9.77,26.44 U60.47 ; U43.8 v1(118.87,127.29) ; J5.A12 v1(31.72,8.87) ; U28.8 v1(80.43,21.16) ; J6.A1 42.33,8.7 v1(42.14,8.9) ; J2.32 100.73,111.17 101,111.43 v1(101.2,111.43) ; U60.51 v1(6.12,24.2) ; U81.1 156.87,102.78 v1(157.09,102.57) ; U34.8 v1(94.73,127.3) ; v1(14.03,16.75) 14.27,16.52 U60.11 ; v1(70.98,124.25) 70.98,124.31 70.86,124.44 U31.3 ; U29.10 159.7,112.31 v1(159.85,112.47) ; U60.13 15.27,14.73 v1(15.15,14.6) ; U37.3 v1(41.87,127.27) ; U33.3 v1(57.14,127.27) ; U37.8 v1(41.87,124.88) ; U50.9 193.71,32.83 v1(194.15,33.27) ; U45.8 v1(105.25,124.88) ; U39.8 v1(32.61,124.88) ; U1.9 182.15,82.61 v1(182.31,82.44) ; U40.3 v1(142.89,124.88) ; U32.3 v1(65.77,127.58) ; U29.24 161.2,107.59 v1(161.5,107.29) ; U41.8 v1(137.84,124.88) ; J6.A12 v1(48.38,8.06) ; U34.3 v1(94.73,124.88) ; J25.39 v1(34.36,59.67) ; U42.8 v1(129.09,124.88) ; v1(117.65,115.94) 117.44,115.94 TP79.1 ; U60.1 v1(9.27,16.74) ; J17.2 v1(155.06,141.53) ; U25.8 v1(100.81,21.16) ; U78.3 17.75,30.75 v1(17.82,30.69) ; U81.3 156.75,103.78 v1(156.96,103.99) ; U50.24 189.56,27.62 v1(188.99,27.05) ; U42.3 v1(129.09,127.27) ; U43.3 v1(118.87,124.88) ; U39.3 v1(32.61,127.27) ; U60.5 11.27,16.5 11.43,16.66 v1(11.43,16.74) ; J17.11 v1(159.55,141.53) ; U40.8 v1(142.89,127.27) ; TP76.1 106.8,117.36 v1(106.51,117.36) ; U36.3 v1(80.8,127.57) ; U32.8 v1(65.77,124.88) ; U25.3 v1(100.81,18.68) ; J17.5 v1(156.55,141.53) ; U29.21 v1(159.7,107.2) ; J5.A1 v1(26.22,8.81) ; U44.8 113.72,124.99 113.61,124.89 v1(113.61,124.88) ; v1(157.22,110.16) 157.29,110.09 U29.15 ; U35.3 v1(89.71,127.34) ; U28.3 v1(80.43,18.67) ; U29.6 162.44,111.09 v1(162.58,111.23) ; U44.3 v1(113.72,127.27) ; U31.8 70.86,127.43 v1(71,127.58) ; U41.3 v1(137.84,127.27) ; U45.3 v1(105.25,127.27) ; U27.8 v1(84.46,21.16) ; U38.8 v1(46.82,127.27) ; J17.17 v1(162.55,141.44) ; J17.8 v1(158.06,141.53) ; U38.3 v1(46.82,124.88) ; U24.3 v1(104.82,18.67) ; U60.35 v1(15.77,26.15) ; U60.15 v1(16.27,14.6)
  TOP w0.305: U79.3 161.38,131.15 v1(161.29,131.24) ; U2.3 177.32,88.52 176.99,88.18 v1(176.99,88.15) ; v1(130.84,56.53) 130.56,56.81 U54.3 ; C75.2 v1(98.18,20.34) ; v1(96.22,28.35) 96.22,28.18 Y1.4 ; R78.2 v1(96.48,20.34) ; U1.18 184.35,86.98 v1(184.43,87.06) ; R104.2 v1(90.12,20.34) ; C80.2 96.71,25.21 v1(96.4,25.21) ; C79.2 97.02,28.46 v1(96.85,28.64) ; U54.6 v1(132.06,56.52) ; R51.2 v1(68.19,32.59) ; J12.B12 v1(59.66,128.51) ; U2.1 v1(176.84,89.52) ; C5.2 v1(176.98,90.17) ; Y1.2 v1(94.33,25.08)
  TOP w0.33: J16.B15 v1(105.24,128.51) ; J14.A12 v1(35.26,133.56) ; J13.B4 v1(90.05,128.51) ; J12.A15 v1(56.86,133.56) ; J13.B15 v1(81.25,128.51) ; J15.B15 v1(129.24,128.51) ; J14.A18 v1(29.9,132.29) ; J14.B7 v1(39.66,128.51) ; J15.B12 v1(131.64,128.51) ; J16.B4 v1(114.04,128.51) ; J15.B7 v1(135.64,128.51) ; J15.B18 v1(126.84,128.51) ; 87.25,132.29 87.25,133.55 v1(87.25,133.56) ; J14.A15 v1(32.86,133.56) ; J15.B1 v1(140.44,128.51) ; J14.A1 v1(44.71,132.29) ; J16.B12 v1(107.64,128.51) ; J14.B15 v1(33.26,128.51) ; J16.A15 v1(104.84,133.56) ; J16.A1 v1(116.6,132.29) ; J16.A4 v1(113.64,133.56) ; J14.B12 v1(35.66,128.51) ; J13.A12 v1(83.25,133.56) ; J14.B18 v1(30.86,128.51) ; J12.B4 v1(66.06,128.51) ; J13.B18 v1(78.85,128.51) ; J13.A15 v1(80.85,133.56) ; J13.B1 v1(92.45,128.51) ; J16.A7 v1(111.24,133.56) ; J14.B4 v1(42.06,128.51) ; J14.A7 v1(39.26,133.56) ; J12.A1 v1(68.71,132.29) ; J13.A18 v1(78.45,133.56) ; J16.B18 v1(102.84,128.51) ; J12.A12 v1(59.26,133.56) ; J15.A18 v1(126.44,133.56) ; J15.B4 v1(138.04,128.51) ; J16.A12 v1(107.24,133.56) ; J12.B1 v1(68.46,128.51) ; J15.A1 v1(140.6,132.29) ; J16.B1 v1(116.44,128.51) ; J12.A7 v1(63.26,133.56) ; J16.B7 v1(111.64,128.51) ; J12.B7 v1(63.66,128.51) ; J13.A4 v1(89.65,133.56) ; J15.A4 v1(137.64,133.56) ; J12.A18 v1(53.9,132.29) ; J15.A12 v1(131.24,133.56) ; J15.A15 v1(128.84,133.56) ; J12.B18 v1(54.86,128.51) ; J15.A7 v1(135.24,133.56) ; J14.B1 v1(44.46,128.51) ; J14.A4 v1(41.66,133.56) ; J12.A4 v1(65.66,133.56) ; J13.B12 v1(83.65,128.51) ; J16.A18 v1(102.44,133.56) ; J13.B7 v1(87.65,128.51) ; J12.B15 v1(57.26,128.51) ; J13.A1 v1(92.61,132.29)
  TOP w0.381: C235.2 v1(184.2,52.71) ; v1(78.41,24.32) 78.28,24.19 C98.2 ; TP72.1 v1(150.09,18.38) ; TP72.1 v1(150.09,22.84) ; TP72.1 v1(152.99,20.63) ; TP72.1 v1(147.32,20.63) ; v1(164.96,109.38) 164.47,108.9 C111.2 ; Y2.2 v1(74.33,24.59) ; v1(184.07,20.15) 184.29,19.92 C200.2 ; C232.2 v1(180.35,61.46) ; D12.2 v1(164.05,136.6) ; X1.4 v1(6.3,13) ; v1(42.95,22.89) 43.15,22.68 C35.2 ; Y3.2 v1(167.1,110.03) ; C45.2 40.71,14.79 v1(40.71,14.79) ; v1(197.04,22.32) 196.8,22.56 C189.2 ; C219.2 138.72,37.34 v1(138.73,37.35) ; Q1.2 v1(27.32,20.49) ; R126.2 v1(81.62,35.32) ; C101.2 v1(74.84,29.86) ; C218.1 v1(138.75,39.49) ; R124.2 v1(83.95,35.33) ; v1(69.87,40.91) 69.28,40.32 R52.2 ; R45.2 v1(26.52,19.27) ; v1(40.79,26.63) 41.08,26.63 C57.1 ; C164.2 24.54,25.12 v1(24.35,24.93) ; R95.2 v1(105.82,37.12) ; C29.1 v1(35.98,20.51) ; C193.2 199.42,32.44 v1(199.79,32.81) ; C229.2 v1(184.35,78.81) ; C206.1 v1(133.28,19.73) ; v1(76.6,27.11) 76.6,26.46 Y2.4 ; R96.2 v1(102.58,37.12) ; v1(16.42,33.95) C331.2 15.91,35.58 C330.2 ; C83.2 v1(94.1,30.26) ; C216.2 v1(168.15,21.46) ; v1(175.69,131.97) 175.69,130.77 TP75.1 ; C196.2 v1(184.49,31.28) ; TP112.1 v1(68.3,125.05) ; U13.2 v1(42.05,19.74) ; C163.2 v1(26.55,17.09) ; v1(15.92,38.36) C329.2 15.92,37.72 C328.2 ; TP115.1 v1(140.35,126.9) ; C251.2 v1(15.77,12.48) ; R457.2 v1(180.8,120.89) ; v1(42.13,16.61) 42.13,16.98 R49.1 ; TVS5.1 v1(192.13,16.45) ; C233.2 v1(183.77,61.48) ; C175.2 v1(190.65,23.51) ; R121.2 v1(74.85,33.03) ; v1(12.85,8.8) TVS7.1 v1(12.04,9.48) ; R287.2 v1(8.9,123.9) ; R65.2 50.51,26.95 v1(50.51,27) ; U74.2 v1(5.09,30.68) ; R288.2 v1(7.63,123.89) ; C337.2 v1(129.4,60.72) ; R445.2 v1(177.8,84.2) ; R94.2 v1(94.1,32.44) ; D13.2 v1(162.42,136.66) ; R217.1 v1(135.41,42.25) ; Q2.2 v1(50.58,23.7) ; TVS3.1 v1(199.72,16.37) ; v1(46.71,28.19) 46.77,28.25 C51.1 ; C231.2 v1(184.7,96.53) ; C171.2 v1(170.98,130.01) ; C207.2 v1(139.23,22.33) ; C81.2 v1(98.44,37.18) ; R112.2 v1(76.39,22.58) ; X1.2 v1(10.49,10.39) ; R176.2 162.33,133.22 v1(161.95,133.6) ; C32.2 67.34,40.31 v1(67.89,40.87) ; C174.2 v1(198.74,27.28) ; v1(97.59,23.08) 97.53,23.08 R81.2 ; R248.2 v1(24.15,133.04) ; v1(72.21,32.42) R5.2 v1(71.41,31.69) ; C30.2 v1(37.11,19.39) ; v1(2.95,18.39) C239.2 v1(2.1,17.43) ; U59.2 v1(3.85,12.79) ; v1(77.94,27.27) 77.78,27.1 C97.2 ; C99.2 v1(79.16,37.56) ; R289.2 v1(6.37,123.89) ; v1(163.09,129.44) C169.2 163.09,128.66 C168.2 ; C176.1 v1(196.7,21.7) ; C324.2 v1(3.23,27.32) ; U12.2 v1(68.36,36.33) ; R122.2 v1(74.85,28.81) ; v1(30.36,23.8) 30.36,23.29 29.45,22.39 R44.2 ; C223.1 v1(196.25,125.52) ; v1(183.86,27.26) 183.94,27.18 C201.2 ; C158.2 v1(171.42,135.85) ; R98.2 v1(99.53,34.71) ; D15.3 v1(165.95,15.24) ; R92.2 v1(94.1,34.67) ; v1(15.98,30.81) 15.5,31.3 C346.2 ; C240.2 v1(5.54,17.01) ; C234.2 v1(180.73,52.69) ; v1(196.82,16.35) TVS6.1 ; C15.2 v1(184.58,25.19) ; C192.2 v1(198.13,28.52) ; C348.2 v1(177.99,119.13) ; v1(136.57,19.73) 136.58,19.74 C208.2 ; R330.2 v1(12.22,12.13) ; v1(200.37,101.51) C226.2 v1(201.26,102.56) ; R290.2 v1(5.1,123.88) ; TP114.1 v1(116.35,127.26) ; C190.2 v1(195.53,22.9) ; C31.1 v1(27.79,17.1) ; C194.1 v1(183.93,28.25) ; R109.2 v1(76.01,20.34) ; U51.5 v1(133.33,32.8) ; C100.2 v1(74.84,32) ; R128.2 v1(86.53,35.34) ; R209.2 v1(185.4,20.09) ; C27.2 v1(26.09,14.68) ; C54.2 49.9,27.98 v1(50.12,28.2) ; v1(137.42,30.39) 137.14,30.67 U51.2 ; J22.7 v1(188.78,132.5) ; R97.2 v1(100.61,34.74) ; C253.2 v1(10.29,13.79) ; 16.41,4.38 v1(16.41,5.61) ; C82.2 v1(94.1,33.59) ; C110.2 v1(164.4,107.04) ; R93.2 v1(94.1,31.34) ; R247.2 v1(24.12,130.49) ; v1(13.77,40.11) 13.92,39.96 R430.1 ; C181.1 v1(198.15,30.73) ; Q17.2 v1(181.08,122.4) ; Q7.2 v1(182.14,19.73) ; C228.2 v1(180.84,78.79) ; v1(91.48,35.4) 91.48,35.01 R438.2 ; C336.2 v1(131.38,60.73) ; J21.9 v1(188.45,92.8) ; C11.2 v1(180.88,105.2) ; TP80.1 v1(94.62,40.6) ; J22.8 v1(194.38,132.5) ; R141.1 v1(161.38,104.11) ; v1(185.59,101.03) C224.2 v1(184.72,101.84) ; R322.1 v1(121.37,32.58) ; C55.2 C56.2 v1(48.18,20.77) ; v1(78.08,35.32) R119.2 ; Y3.4 v1(165.83,106.54) ; R444.2 v1(177.77,85.29) ; C170.2 v1(169.88,130.04) ; C215.2 v1(162.2,23.92) ; R218.1 v1(138.76,35.14) ; R190.1 v1(193.77,20.34) ; R125.2 v1(82.83,35.33) ; D10.2 v1(167.31,136.56) ; TP111.1 v1(44.33,126.94) ; TVS4.1 v1(189.23,16.43) ; C217.2 v1(138.73,38.37) ; C214.1 v1(163.57,21.44) ; C179.2 v1(190.51,22.31) ; D14.3 v1(134.94,14.14) ; U48.4 v1(166.69,125.25) ; R99.2 v1(108.21,35.17) ; R57.1 v1(63.55,33.66) ; R196.2 v1(192.68,20.34) ; C220.1 v1(138.75,36.24) ; C326.2 v1(6.02,35.53) ; C182.2 v1(200.78,28.64) ; C34.2 v1(36.95,20.68) ; D11.2 v1(165.7,136.58) ; C252.2 v1(6.86,14.36) ; v1(71.42,39.08) 71.42,38.09 v1(70.43,38.09) ; D25.C v1(5.79,141.74) ; R123.2 v1(74.85,30.92) ; TP113.1 v1(92.24,125.2) ; TP77.1 v1(175.83,52.98) ; C94.2 v1(78.52,20.34) ; C10.2 v1(178.68,105.2) ; C198.1 v1(188.66,20.32) ; C230.2 v1(181.19,96.53) ; C345.2 v1(163.92,131.89)
  BOTTOM w0.203: v1(21.89,100.92) 21.95,100.92 22.23,100.64 U49.8 ; v1(22.02,97.64) 22.03,97.64 22.23,97.85 U49.3 ; U20.6 v1(7.85,77.97) ; U8.6 8.43,47.55 v1(8.56,47.42) ; U49.12 v1(24.23,100.4) ; U7.6 v1(14.11,47.53)
  BOTTOM w0.254: U3.22 136.32,84.43 v1(136.38,84.49) ; U3.13 v1(134.49,89.81) ; R351.2 23.64,67.3 v1(23.15,67.79) ; C263.2 v1(39.21,61.46) ; U70.9 14.16,69.32 v1(14.22,69.27) ; v1(9.97,66.37) 10.16,66.56 U70.18 ; J10.7 v1(162.22,98.42) ; v1(21.95,74.16) 21.71,73.92 U66.3 ; v1(110.42,83.47) 110.57,83.62 U52.3 ; U6.6 v1(113.18,93.75) ; U63.10 v1(40.73,64.54) ; J10.1 v1(163.72,98.42) ; U3.11 v1(131.94,88.96) ; U63.2 v1(43.41,66.47) ; U3.12 v1(132.99,89.81)
  BOTTOM w0.305: v1(22.41,67.59) 22.28,67.47 U67.3 ; J10.75 v1(145.22,98.42) ; J10.51 v1(151.22,98.42) ; J10.18 v1(159.47,88.37) ; J10.69 v1(146.72,98.42) ; J10.39 v1(154.22,98.42) ; J10.63 148.22,98.2 v1(148.44,98.42) ; J10.33 v1(155.72,96.11) ; J10.45 v1(152.72,98.42) ; J10.57 v1(149.72,98.42) ; U52.6 v1(109.07,83.5)
  BOTTOM w0.381: v1(10.44,24.4) 9.89,24.4 C297.2 ; J11.6 v1(178.89,136.36) ; v1(136.74,77.68) 136.74,77.68 C343.2 ; R427.2 v1(14.13,79.47) ; C309.2 v1(8.04,53.16) ; C327.2 v1(20.66,64.31) ; C244.2 v1(16.33,19.84) ; C308.1 v1(18.09,49.38) ; C283.1 v1(24.59,101.93) ; C300.2 v1(14.79,24.15) ; R446.2 v1(18.05,102.2) ; C265.2 v1(38.18,66.52) ; U80.4 28.85,56.63 v1(28.5,56.97) ; R278.2 v1(27.82,97.47) ; C245.2 v1(12.29,24.16) ; C204.2 v1(134.04,27.33) ; Q12.2 v1(19.89,57.28) ; C242.2 v1(10.79,18.71) ; C7.2 v1(132.99,80.87) ; C322.1 v1(14.12,77.31) ; v1(3.85,12.79) 3.95,12.69 C236.2 ; C243.2 v1(11.32,23.14) ; R34.2 136.04,77.8 v1(135.82,77.58) ; C306.1 v1(12.9,53.16) ; v1(135.22,30.49) 135.41,30.68 C203.2 ; C339.2 v1(86.79,31.05) ; C320.2 6.49,67.06 v1(6.04,67.51) ; v1(137.27,83.15) 137.53,83.41 C9.2 ; v1(10.46,25.25) 10.12,25.25 C294.2 ; C318.2 v1(6.07,71.66) ; C8.2 v1(134.75,80.87) ; C319.2 v1(6.05,68.16) ; v1(109.69,87.61) 109.84,87.46 C33.2 ; C246.2 v1(15.75,24.68) ; C205.2 v1(135.11,27.36) ; C241.2 v1(13.26,18.72) ; R38.2 47.41,15.24 v1(47.7,15.52) ; v1(27.08,46.37) 27.55,46.83 R443.1 ; Q15.2 137.49,77.08 v1(137.36,77.21) ; Q13.2 v1(134.63,76.91) ; C299.2 v1(14.77,18.74) ; C77.2 97.64,31.48 C76.2 v1(96.93,32.59) ; C113.2 v1(145.08,85.88) ; C70.2 v1(97.12,30.17) ; R450.2 v1(17.01,97.6) ; C317.2 v1(6.07,70.6) ; C296.2 v1(10.38,21.72) ; C310.1 v1(9.88,52.55) ; R259.2 v1(47.35,63.99) ; C13.2 v1(108.47,92.01) ; R383.1 v1(23.29,48.23) ; v1(113.2,87.01) C37.2 ; R280.2 v1(27.81,98.6) ; C238.2 v1(2.78,12.84) ; v1(18.92,73.72) 19.05,73.59 C335.2 ; R453.2 v1(30.92,15.15) ; C321.2 v1(14.12,78.38) ; R409.1 v1(22.15,69.9) ; v1(13.79,53.19) 13.97,53.02 C305.2 ; Q11.2 v1(20.67,48.77) ; v1(136.33,30.5) 136.5,30.68 C202.2 ; C237.2 v1(5.11,12.79) ; D24.A v1(36.9,65.49) ; C12.2 v1(108.46,95.46) ; C112.2 v1(143.99,85.85) ; R260.2 v1(38.58,65.48) ; C338.2 v1(25.72,46.9) ; R347.2 v1(6.35,52.55) ; C295.2 10.3,26.19 v1(10.3,26.08) ; C6.2 v1(131.92,80.87) ; C298.2 v1(9.73,18.43) ; C332.1 v1(27.88,101.91) ; C307.2 v1(17.41,51.07) ; TVS1.1 v1(175.69,131.97)
  vias: v1(0.93,147.65) v1(0.93,146.38) v1(0.93,145.11) v1(0.93,143.84) v1(0.93,142.57) v1(0.93,141.3) v1(0.93,140.03) v1(0.93,138.76) v1(0.93,137.49) v1(0.93,136.22) v1(0.93,134.95) v1(0.93,133.68) v1(0.93,132.41) v1(0.93,131.14) v1(0.93,129.87) v1(0.93,128.6) v1(0.93,127.33) v1(0.93,126.06) v1(0.93,124.79) v1(0.93,123.52) v1(0.93,122.25) v1(0.93,120.98) v1(0.93,119.71) v1(0.93,118.44) v1(0.93,117.17) v1(0.93,115.9) v1(0.93,114.63) v1(0.93,113.36) v1(0.93,112.09) v1(0.93,110.82) v1(0.93,109.55) v1(0.93,108.28) v1(0.93,107.01) v1(0.93,105.74) v1(0.93,104.47) v1(0.93,103.2) v1(0.93,101.93) v1(0.93,100.66) v1(0.93,99.39) v1(0.93,98.12) v1(0.93,96.85) v1(0.93,95.58) v1(0.93,94.31) v1(0.93,93.04) v1(0.93,91.77) v1(0.93,90.5) v1(0.93,89.23) v1(0.93,87.96) v1(0.93,86.69) v1(0.93,85.42) v1(0.93,84.15) v1(0.93,82.88) v1(0.93,81.61) v1(0.93,80.34) v1(0.93,79.07) v1(0.93,77.8) v1(0.93,76.53) v1(0.93,75.26) v1(0.93,73.99) v1(0.93,72.72) v1(0.93,71.45) v1(0.93,70.18) v1(0.93,68.91) v1(0.93,67.64) v1(0.93,66.37) v1(0.93,65.1) v1(0.93,63.83) v1(0.93,62.56) v1(0.93,61.29) v1(0.93,60.02) v1(0.93,58.75) v1(0.93,57.48) v1(0.93,56.21) v1(0.93,54.94) v1(0.93,53.67) v1(0.93,52.4) v1(0.93,51.13) v1(0.93,49.4) v1(0.93,48.13) v1(0.93,46.93) v1(0.93,45.66) v1(0.93,44.39) v1(0.93,43.12) v1(0.93,41.85) v1(0.93,40.58) v1(0.93,39.31) v1(0.93,38.04) v1(0.93,36.77) v1(0.97,35.4) v1(0.97,34.13) v1(0.97,32.93) v1(0.97,31.66) v1(0.97,30.39) v1(0.97,29.12) v1(0.97,27.85) v1(0.97,26.58) v1(0.97,25.31) v1(0.97,24.04) v1(0.97,22.77) v1(0.97,21.53) v1(0.97,20.26) v1(0.97,19.06) v1(0.97,17.79) v1(0.97,16.52) v1(0.97,15.25) v1(0.97,13.98) v1(0.97,12.71) v1(0.97,11.44) v1(0.97,10.17) v1(0.97,8.9) v1(1.08,6.88) v1(1.29,5.11) v1(1.35,148.69) v1(1.78,3.38) v1(1.91,149.5) v1(2.04,44.41) v1(2.04,43.14) v1(2.04,41.87) v1(2.04,40.08) v1(2.04,38.81) v1(2.04,37.54) v1(2.03,32.53) v1(2.03,31.26) v1(2.03,29.99) v1(2.03,28.72) v1(2.03,27.45) v1(2.03,26.18) v1(2.03,24.91) v1(2.03,23.64) v1(2.03,22.37) v1(2.03,21.13) v1(2.03,19.86) v1(2.03,18.66) v1(2.12,144.72) v1(2.08,62.55) v1(2.08,61.28) v1(2.08,60.01) v1(2.08,58.74) v1(2.08,57.47) v1(2.08,56.2) v1(2.08,54.93) v1(2.08,53.66) v1(2.08,52.39) v1(2.08,51.12) v1(2.08,49.85) v1(2.08,48.58) v1(2.08,46.85) v1(2.08,45.58) v1(2.3,143.38) v1(2.26,140.03) v1(2.26,138.76) v1(2.26,137.49) v1(2.26,136.22) v1(2.26,134.95) v1(2.26,133.68) v1(2.26,132.41) v1(2.26,131.14) v1(2.26,129.87) v1(2.26,128.6) v1(2.26,127.33) v1(2.26,126.06) v1(2.26,124.79) v1(2.26,123.52) v1(2.26,122.25) v1(2.26,120.98) v1(2.26,119.71) v1(2.26,118.44) v1(2.26,117.17) v1(2.26,115.9) v1(2.26,114.63) v1(2.26,113.36) v1(2.26,112.09) v1(2.26,110.82) v1(2.26,109.55) v1(2.26,108.28) v1(2.26,107.01) v1(2.26,105.74) v1(2.26,104.47) v1(2.26,103.2) v1(2.26,101.93) v1(2.26,100.66) v1(2.26,99.39) v1(2.26,98.12) v1(2.26,96.85) v1(2.26,95.58) v1(2.26,94.31) v1(2.26,93.04) v1(2.26,91.77) v1(2.26,90.5) v1(2.26,89.23) v1(2.26,87.96) v1(2.26,86.69) v1(2.26,85.42) v1(2.26,84.15) v1(2.26,82.88) v1(2.26,81.61) v1(2.26,80.34) v1(2.28,79.08) v1(2.28,77.81) v1(2.28,76.54) v1(2.28,75.27) v1(2.28,74) v1(2.28,72.73) v1(2.28,71.46) v1(2.28,70.19) v1(2.28,68.92) v1(2.28,67.65) v1(2.28,66.38) v1(2.28,65.11) v1(2.28,63.84) v1(2.65,150.37) v1(2.67,36.21) v1(3.06,1.86) v1(3.19,38.81) v1(3.19,37.54) v1(3.25,62.53) v1(3.25,61.26) v1(3.25,59.99) v1(3.25,58.72) v1(3.25,57.45) v1(3.25,56.18) v1(3.25,54.91) v1(3.25,53.64) v1(3.25,52.37) v1(3.25,51.1) v1(3.25,49.83) v1(3.25,48.56) v1(3.25,46.83) v1(3.25,45.56) v1(3.25,44.36) v1(3.25,43.09) v1(3.25,41.82) v1(3.25,40.55) v1(3.57,143.38) v1(3.58,138.67) v1(3.58,137.4) v1(3.58,136.13) v1(3.58,134.86) v1(3.58,133.59) v1(3.58,132.32) v1(3.58,131.05) v1(3.58,129.78) v1(3.58,128.51) v1(3.58,127.24) v1(3.58,125.97) v1(3.58,124.7) v1(3.58,123.43) v1(3.58,122.16) v1(3.58,120.89) v1(3.58,119.62) v1(3.58,118.35) v1(3.58,117.08) v1(3.58,115.81) v1(3.58,114.54) v1(3.58,113.27) v1(3.58,112) v1(3.58,110.73) v1(3.58,109.46) v1(3.58,108.19) v1(3.58,106.92) v1(3.58,105.65) v1(3.58,104.38) v1(3.58,103.11) v1(3.58,101.84) v1(3.58,100.57) v1(3.58,99.3) v1(3.58,98.03) v1(3.58,96.76) v1(3.58,95.49) v1(3.58,94.22) v1(3.58,92.95) v1(3.58,91.68) v1(3.58,90.41) v1(3.58,89.14) v1(3.58,87.87) v1(3.58,86.6) v1(3.58,85.33) v1(3.58,84.06) v1(3.58,82.79) v1(3.58,81.52) v1(3.58,80.25) v1(3.66,150.97) v1(3.99,67.85) v1(4.56,1.3) v1(4.84,143.38) v1(4.78,130.78) v1(4.8,129.28) v1(4.94,151.4) v1(5.12,137.84) v1(5.17,41.51) v1(5.17,40.24) v1(5.17,38.97) v1(5.17,37.7) v1(5.28,21.95) v1(5.84,1.05) v1(6.05,130.78) v1(6.11,143.38) v1(6.07,129.28) v1(6.39,81.66) v1(6.46,151.5) v1(6.52,50.64) v1(6.82,2.07) v1(7,137.79) v1(7.11,121.76) v1(7.11,120.49) v1(7.11,119.22) v1(7.11,117.95) v1(7.11,116.68) v1(7.11,115.41) v1(7.11,114.14) v1(7.11,112.47) v1(7.11,111.2) v1(7.11,109.93) v1(7.11,108.66) v1(7.11,107.39) v1(7.11,106.12) v1(7.11,104.85) v1(7.07,102.75) v1(7.07,101.48) v1(7.07,100.21) v1(7.07,98.94) v1(7.07,97.67) v1(7.07,96.4) v1(7.07,95.13) v1(7.11,1.05) v1(7.32,130.78) v1(7.34,129.28) v1(7.29,60.64) v1(7.29,59.37) v1(7.29,58.1) v1(7.29,56.83) v1(7.38,143.38) v1(7.73,151.5) v1(8,39.47) v1(8,38.2) v1(8,36.93) v1(8,35.66) v1(8.09,2.07) v1(8.38,1.05) v1(8.46,60.62) v1(8.46,59.35) v1(8.46,58.08) v1(8.46,56.81) v1(8.51,28.87) v1(8.51,27.6) v1(8.59,130.78) v1(8.61,129.28) v1(8.78,20.48) v1(8.78,19.21) v1(8.86,149.36) v1(8.86,148.09) v1(8.86,146.82) v1(8.86,145.55) v1(8.86,144.28) v1(8.86,143.01) v1(8.86,141.74) v1(8.86,140.47) v1(8.86,139.2) v1(9,151.5) v1(9.53,42.17) v1(10.05,132.33) v1(10.05,131.06) v1(10.05,129.79) v1(10.05,128.52) v1(10.24,103.28) v1(10.18,75.23) v1(10.27,151.5) v1(10.26,107.33) v1(10.26,105.48) v1(10.26,100.98) v1(10.26,98.44) v1(10.4,125.69) v1(10.4,124.42) v1(10.4,123.15) v1(10.4,121.88) v1(10.4,120.61) v1(10.4,119.34) v1(10.4,118.07) v1(10.4,116.8) v1(10.52,68.21) v1(10.64,92.36) v1(10.64,91.09) v1(10.64,89.82) v1(10.64,88.55) v1(10.64,87.28) v1(10.64,86.01) v1(10.64,84.74) v1(10.58,69.93) v1(10.75,136.28) v1(10.78,50.98) v1(10.92,1.05) v1(11,80.29) v1(10.96,48.47) v1(11.38,132.33) v1(11.38,131.06) v1(11.38,129.79) v1(11.38,128.52) v1(11.41,69.07) v1(11.54,151.5) v1(11.52,149.27) v1(11.52,148) v1(11.52,146.73) v1(11.52,145.46) v1(11.52,144.19) v1(11.52,142.92) v1(11.52,141.65) v1(11.52,140.38) v1(11.52,139.11) v1(11.93,75.1) v1(11.87,21.22) v1(11.87,19.95) v1(12.02,136.28) v1(12.04,93.1) v1(12.04,91.83) v1(12.04,90.56) v1(12.04,89.29) v1(12.04,88.02) v1(12.04,86.75) v1(12.04,85.48) v1(12.04,84.21) v1(12.31,69.97) v1(12.28,68.21) v1(12.28,28.49) v1(12.52,125.69) v1(12.52,124.42) v1(12.52,123.15) v1(12.52,121.88) v1(12.52,120.61) v1(12.52,119.34) v1(12.52,118.07) v1(12.52,116.8) v1(12.52,98.65) v1(12.74,105.47) v1(12.67,103.34) v1(12.7,100.98) v1(12.68,42.12) v1(12.81,151.5) v1(12.76,107.35) v1(13.27,137.77) v1(13.29,136.28) v1(13.33,2.16) v1(13.41,92.99) v1(13.41,91.72) v1(13.41,90.45) v1(13.41,89.18) v1(13.41,87.91) v1(13.41,86.64) v1(13.41,85.37) v1(13.46,1.05) v1(13.8,21.18) v1(13.8,19.91) v1(14.04,149.27) v1(14.04,148) v1(14.04,146.73) v1(14.04,145.46) v1(14.04,144.19) v1(14.04,142.92) v1(14.04,141.65) v1(14.04,140.38) v1(14.04,139.11) v1(14.08,151.5) v1(14.54,137.77) v1(14.56,136.28) v1(14.6,2.16) v1(14.72,93.03) v1(14.72,91.76) v1(14.72,90.49) v1(14.72,89.22) v1(14.72,87.95) v1(14.72,86.68) v1(14.72,85.41) v1(14.73,1.05) v1(14.87,124.2) v1(14.87,122.93) v1(14.87,121.66) v1(14.87,120.39) v1(14.87,119.12) v1(14.87,117.85) v1(14.87,116.58) v1(15.02,75.22) v1(15.05,5.79) v1(15.21,103.34) v1(15.24,100.98) v1(15.35,151.5) v1(15.3,107.35) v1(15.28,105.47) v1(15.4,83.03) v1(15.64,28.62) v1(15.81,137.77) v1(15.83,136.28) v1(15.92,142.88) v1(15.92,141.61) v1(15.92,140.34) v1(15.92,139.07) v1(16.37,93.84) v1(16.37,92.57) v1(16.37,91.3) v1(16.37,90.03) v1(16.37,88.76) v1(16.37,87.49) v1(16.37,86.22) v1(16.45,6.84) v1(16.62,151.5) v1(16.94,82.92) v1(16.98,10.31) v1(17.08,137.77) v1(17.1,136.28) v1(17.7,93.84) v1(17.7,92.57) v1(17.7,91.3) v1(17.7,90.03) v1(17.7,88.76) v1(17.7,87.49) v1(17.7,86.22) v1(17.89,151.62) v1(17.94,141.63) v1(17.94,140.36) v1(17.94,139.09) v1(17.96,142.97) v1(18.35,137.77) v1(18.37,136.28) v1(18.41,2.52) v1(18.42,1.1) v1(18.54,7.21) v1(18.51,5.77) v1(18.56,4.14) v1(18.82,16.34) v1(19.04,14.62) v1(18.97,12.67) v1(18.99,10.34) v1(19.16,151.62) v1(19.64,136.28) v1(19.68,2.52) v1(19.69,1.1) v1(19.81,7.21) v1(19.78,5.77) v1(19.83,4.14) v1(20.01,142.7) v1(20.01,141.43) v1(20.01,140.16) v1(20.01,138.89) v1(20.01,137.62) v1(19.95,17.35) v1(20.34,46.89) v1(20.34,45.5) v1(20.43,151.62) v1(20.88,19.84) v1(21.05,12.72) v1(20.95,2.52) v1(20.96,1.1) v1(21.11,14.67) v1(21.07,10.38) v1(21.08,7.21) v1(21.05,5.77) v1(21.1,4.14) v1(21.34,88.19) v1(21.33,86.39) v1(21.3,80.04) v1(21.34,77.16) v1(21.32,28.86) v1(21.36,89.93) v1(21.7,151.5) v1(21.7,122.03) v1(22.07,57.28) v1(22.22,2.52) v1(22.23,1.1) v1(22.35,7.21) v1(22.32,5.77) v1(22.37,4.14) v1(22.62,24.71) v1(22.83,14.64) v1(22.76,12.69) v1(22.79,10.36) v1(22.97,151.5) v1(23.59,80.06) v1(23.56,76.93) v1(23.69,42.1) v1(23.67,40.37) v1(23.66,38.56) v1(24.24,151.5) v1(24.24,150.39) v1(24.4,4.19) v1(24.52,89.75) v1(24.5,88.01) v1(24.49,86.21) v1(25.08,10.73) v1(25.51,151.5) v1(25.51,150.39) v1(25.66,124.37) v1(25.68,119.7) v1(26.03,64.25) v1(26.22,2.45) v1(26.16,1.05) v1(26.31,4.09) v1(26.78,151.5) v1(26.78,150.39) v1(27.04,64.24) v1(27.43,1.05) v1(27.49,2.45) v1(27.58,4.09) v1(28.05,151.5) v1(28.43,64.23) v1(28.7,76.19) v1(28.7,1.05) v1(28.84,79.76) v1(28.76,2.45) v1(28.85,4.09) v1(29.32,151.5) v1(29.32,150.39) v1(29.49,90.02) v1(29.46,87.29) v1(29.71,98.68) v1(29.71,95.31) v1(29.86,24.23) v1(30.03,2.45) v1(29.97,1.05) v1(30.12,4.09) v1(30.48,56.63) v1(30.59,151.5) v1(30.59,150.39) v1(30.79,24.23) v1(31.05,124.87) v1(31.24,1.05) v1(31.31,137.65) v1(31.45,72.2) v1(31.59,98.63) v1(31.59,95.27) v1(31.69,14.22) v1(31.78,79.94) v1(31.78,76.28) v1(31.86,151.5) v1(31.86,150.39) v1(31.86,18.58) v1(32.12,92.77) v1(32.08,89.94) v1(32.08,87.4) v1(32.46,137.64) v1(32.53,18.21) v1(32.51,1.05) v1(32.91,65.72) v1(33.13,151.5) v1(33.13,150.39) v1(33.22,114.13) v1(33.15,109.46) v1(33.18,72.18) v1(33.42,136.24) v1(33.44,40.43) v1(33.43,38.63) v1(33.52,111.66) v1(33.46,42.17) v1(33.74,95.15) v1(33.84,117.48) v1(33.78,98.59) v1(34.08,124.85) v1(34.1,46.42) v1(34.18,48.5) v1(34.28,101.86) v1(34.32,79.94) v1(34.32,76.28) v1(34.4,151.5) v1(34.4,150.39) v1(34.37,103.92) v1(34.69,137.6) v1(34.89,109.44) v1(34.95,114.11) v1(34.99,72.17) v1(35.11,2.25) v1(35.05,1.05) v1(35.34,92.6) v1(35.31,90.03) v1(35.31,87.49) v1(35.32,8.31) v1(35.32,6.94) v1(35.32,5.61) v1(35.54,111.63) v1(35.67,151.5) v1(35.67,150.39) v1(35.94,123.07) v1(35.85,117.46) v1(36.11,27.13) v1(36.3,101.84) v1(36.32,98.59) v1(36.28,95.15) v1(36.32,1.05) v1(36.39,103.9) v1(36.38,2.25) v1(36.59,8.31) v1(36.59,6.94) v1(36.59,5.61) v1(36.69,109.43) v1(36.76,114.09) v1(36.94,151.5) v1(36.94,150.39) v1(36.91,121.32) v1(37.14,79.9) v1(37.14,76.24) v1(37.27,27.1) v1(37.65,2.25) v1(37.59,1.05) v1(37.96,123.04) v1(38.21,151.5) v1(38.21,150.39) v1(38.22,92.68) v1(38.18,89.85) v1(38.18,87.31) v1(38.21,51.61) v1(38.19,49.52) v1(38.31,117.44) v1(38.31,116.11) v1(38.52,27.13) v1(38.92,121.29) v1(38.92,2.25) v1(38.86,1.05) v1(39.35,95.16) v1(39.48,151.5) v1(39.48,150.39) v1(39.58,117.44) v1(39.58,116.11) v1(39.8,98.5) v1(40.24,124.83) v1(40.31,137.57) v1(40.75,151.5) v1(40.75,150.39) v1(40.75,51.61) v1(40.73,49.52) v1(40.83,89.88) v1(40.83,87.34) v1(40.85,117.44) v1(40.85,116.11) v1(40.87,92.7) v1(41.74,76.6) v1(41.73,74.8) v1(41.8,136.25) v1(41.76,78.34) v1(41.86,137.58) v1(41.87,98.41) v1(41.86,1.05) v1(42.02,151.5) v1(42.02,150.39) v1(42.12,117.44) v1(42.12,116.11) v1(42.62,95.18) v1(42.82,2.23) v1(43.06,1.05) v1(43.18,86.86) v1(43.29,151.5) v1(43.29,150.39) v1(43.38,92.74) v1(43.38,89.96) v1(43.49,124.94) v1(43.55,49.47) v1(43.57,51.57) v1(43.8,14.45) v1(44.03,9.04) v1(44.09,2.23) v1(44.33,1.05) v1(44.54,27.01) v1(44.56,151.5) v1(44.56,150.39) v1(44.85,78.24) v1(44.83,76.51) v1(44.82,74.7) v1(44.95,40.53) v1(44.93,38.73) v1(44.96,42.27) v1(45.07,120.7) v1(45.13,13.15) v1(45.09,11.33) v1(45.18,26.48) v1(45.34,15.52) v1(45.38,17.35) v1(45.37,14.1) v1(45.36,2.23) v1(45.6,1.05) v1(45.83,151.5) v1(45.83,150.39) v1(45.98,110.8) v1(46,10.16) v1(46.58,13.95) v1(46.63,2.23) v1(46.93,120.67) v1(46.87,1.05) v1(47.1,151.5) v1(47.1,150.39) v1(47.32,90.8) v1(47.32,88.26) v1(47.37,93.62) v1(47.44,11.02) v1(47.52,109.09) v1(48.14,1.05) v1(48.37,151.5) v1(48.37,150.39) v1(48.37,116.29) v1(48.77,107.16) v1(48.81,105.9) v1(48.91,108.99) v1(48.92,17) v1(49.41,90.77) v1(49.41,88.23) v1(49.45,10.37) v1(49.46,93.6) v1(49.64,151.5) v1(49.64,150.39) v1(49.55,14.59) v1(49.84,104.07) v1(49.75,21.17) v1(49.78,17.12) v1(50.27,78.03) v1(50.27,75.49) v1(50.27,72.95) v1(50.27,70.41) v1(50.27,67.87) v1(50.27,65.33) v1(50.47,105.89) v1(50.58,109.98) v1(50.58,108.66) v1(50.56,21.2) v1(50.72,14.63) v1(50.91,151.5) v1(50.91,150.39) v1(51,17.9) v1(51.24,16.09) v1(51.3,10.3) v1(51.73,124.95) v1(51.73,123.68) v1(51.85,109.98) v1(51.85,108.66) v1(51.94,90.8) v1(51.94,88.26) v1(51.98,93.62) v1(52.18,151.5) v1(52.3,78) v1(52.3,75.46) v1(52.3,72.92) v1(52.3,70.38) v1(52.3,67.84) v1(52.3,65.3) v1(52.53,23.82) v1(52.55,8.88) v1(52.55,6.84) v1(52.55,4.81) v1(52.55,2.78) v1(52.55,1.1) v1(52.7,128.48) v1(52.7,127.21) v1(53,124.95) v1(53,123.68) v1(53.12,109.98) v1(53.12,108.66) v1(53.34,122.19) v1(53.27,106.22) v1(53.45,151.5) v1(53.45,150.39) v1(53.68,42.14) v1(53.67,40.4) v1(53.97,128.48) v1(53.97,127.21) v1(54.03,90.77) v1(54.03,88.23) v1(54.08,93.6) v1(54.08,78.03) v1(54.08,75.49) v1(54.08,72.95) v1(54.08,70.41) v1(54.08,67.87) v1(54.08,65.33) v1(54.18,23.85) v1(54.27,124.95) v1(54.27,123.68) v1(54.39,109.98) v1(54.39,108.66) v1(54.52,60.16) v1(54.5,58.42) v1(54.49,56.62) v1(54.58,8.88) v1(54.58,6.84) v1(54.58,4.81) v1(54.58,2.78) v1(54.58,1.1) v1(54.72,151.5) v1(54.72,150.39) v1(54.74,122.57) v1(54.74,121.3) v1(55.1,23.84) v1(55.42,137.45) v1(55.49,42.11) v1(55.48,40.38) v1(55.61,124.89) v1(55.69,106.51) v1(55.68,60.17) v1(55.66,58.44) v1(55.99,151.5) v1(55.99,150.39) v1(56.01,122.57) v1(56.01,121.3) v1(56.23,120.06) v1(56.49,137.43) v1(56.61,8.88) v1(56.61,6.84) v1(56.61,4.81) v1(56.61,2.78) v1(56.61,1.1) v1(56.82,108.06) v1(56.82,107.45) v1(57.26,151.5) v1(57.26,150.39) v1(57.28,122.57) v1(57.28,121.3) v1(57.44,118.72) v1(57.54,136.22) v1(57.71,96.49) v1(57.72,42.44) v1(57.88,108.09) v1(57.88,107.48) v1(58.53,151.5) v1(58.53,150.39) v1(58.54,120.82) v1(58.55,124.88) v1(58.62,96.51) v1(58.61,31.48) v1(58.65,8.88) v1(58.65,6.84) v1(58.65,4.81) v1(58.65,2.78) v1(58.65,1.1) v1(58.69,119.32) v1(58.69,118.05) v1(58.72,116.72) v1(58.85,137.48) v1(58.88,29.06) v1(58.88,28.38) v1(59.51,96.48) v1(59.46,42.43) v1(59.8,151.5) v1(59.8,150.39) v1(59.79,124.43) v1(59.82,81.48) v1(59.82,78.94) v1(59.82,76.4) v1(59.77,67.27) v1(59.77,64.73) v1(59.77,62.19) v1(59.86,26.46) v1(59.95,121.55) v1(59.95,120.28) v1(59.96,119.32) v1(59.96,118.05) v1(60.26,116.77) v1(60.61,26.45) v1(60.56,23.85) v1(60.56,23.1) v1(60.68,8.88) v1(60.68,6.84) v1(60.68,4.81) v1(60.68,2.78) v1(60.68,1.1) v1(61.07,151.5) v1(61.1,150.48) v1(61.22,121.55) v1(61.22,120.28) v1(61.23,119.32) v1(61.23,118.05) v1(61.26,42.41) v1(61.25,29.06) v1(61.27,28.45) v1(61.63,53.63) v1(61.63,51.09) v1(62.07,118.06) v1(62.07,116.79) v1(62.34,151.5) v1(62.37,150.48) v1(62.71,8.88) v1(62.71,6.84) v1(62.71,4.81) v1(62.71,2.78) v1(62.71,1.1) v1(63.34,118.06) v1(63.34,116.79) v1(63.4,53.66) v1(63.4,51.12) v1(63.61,151.5) v1(63.64,150.48) v1(63.64,30.81) v1(64,137.71) v1(64.24,124.87) v1(64.61,21.78) v1(64.74,8.88) v1(64.74,6.84) v1(64.74,4.81) v1(64.74,2.78) v1(64.74,1.1) v1(64.88,151.5) v1(64.91,150.48) v1(65.36,137.68) v1(65.59,122.66) v1(65.61,17.68) v1(65.75,136.38) v1(66.15,151.5) v1(66.18,150.48) v1(66.22,22.51) v1(66.67,22.03) v1(66.77,8.88) v1(66.77,6.84) v1(66.77,4.81) v1(66.77,2.78) v1(66.77,1.1) v1(67.05,97.77) v1(67.15,136.36) v1(67.29,18.72) v1(67.42,151.5) v1(67.41,122.61) v1(67.37,17.7) v1(67.45,150.48) v1(67.82,120.94) v1(67.77,119.17) v1(67.88,22.1) v1(68.31,25.03) v1(68.69,151.5) v1(68.72,150.48) v1(68.66,98.76) v1(68.81,8.88) v1(68.81,6.84) v1(68.81,4.81) v1(68.81,2.78) v1(68.81,1.1) v1(68.96,19.12) v1(69.21,124.24) v1(69.54,120.6) v1(69.57,118.25) v1(69.7,122.91) v1(69.93,92.27) v1(69.93,91) v1(69.93,89.73) v1(69.93,88.46) v1(69.93,87.19) v1(69.93,85.92) v1(69.93,84.65) v1(69.93,83.38) v1(69.93,82.11) v1(69.93,80.84) v1(69.93,79.57) v1(69.93,78.3) v1(69.93,77.03) v1(69.93,75.76) v1(69.93,74.49) v1(69.93,73.22) v1(69.88,71.67) v1(69.88,70.4) v1(69.88,69.13) v1(69.96,151.5) v1(69.99,150.48) v1(70.08,25.08) v1(70.84,8.88) v1(70.84,6.84) v1(70.84,4.81) v1(70.84,2.78) v1(70.84,1.1) v1(70.94,57.94) v1(70.94,54.13) v1(70.87,51.31) v1(70.98,65.84) v1(70.98,63.3) v1(70.98,60.76) v1(71.07,115.04) v1(71.23,151.5) v1(71.26,150.48) v1(71.83,123.63) v1(71.92,129.59) v1(71.92,128.32) v1(72.37,112.93) v1(72.42,71.67) v1(72.42,70.4) v1(72.42,69.13) v1(72.5,151.5) v1(72.53,150.48) v1(72.47,94.71) v1(72.47,93.44) v1(72.47,92.27) v1(72.47,91) v1(72.47,89.73) v1(72.47,88.46) v1(72.47,87.19) v1(72.47,85.92) v1(72.47,84.65) v1(72.47,83.38) v1(72.47,82.11) v1(72.47,80.84) v1(72.47,79.57) v1(72.47,78.3) v1(72.47,77.03) v1(72.47,75.76) v1(72.47,74.49) v1(72.47,73.22) v1(73.19,129.59) v1(73.19,128.32) v1(73.41,51.31) v1(73.52,65.84) v1(73.52,63.3) v1(73.52,60.76) v1(73.48,57.94) v1(73.48,54.13) v1(73.77,151.5) v1(73.8,150.48) v1(74.26,114.18) v1(74.68,45.47) v1(74.81,99.84) v1(74.81,98.57) v1(74.81,97.3) v1(74.81,96.03) v1(74.81,94.76) v1(74.81,93.49) v1(74.81,92.22) v1(74.81,90.95) v1(74.81,89.68) v1(74.81,88.41) v1(74.81,87.14) v1(74.81,85.87) v1(74.81,84.6) v1(74.81,83.33) v1(74.81,82.06) v1(74.81,80.79) v1(74.81,79.52) v1(74.81,78.25) v1(74.81,76.98) v1(74.81,75.71) v1(74.81,74.44) v1(74.81,73.17) v1(74.77,71.62) v1(74.77,70.35) v1(74.77,69.08) v1(75.04,151.5) v1(75.07,150.48) v1(75.79,101.11) v1(75.89,114.07) v1(76.04,70.38) v1(76.04,69.11) v1(76.24,129.52) v1(76.24,128.25) v1(76.22,71.69) v1(76.31,151.5) v1(76.38,121.07) v1(76.96,114.37) v1(77.06,101.11) v1(77.17,44.5) v1(77.31,70.38) v1(77.31,69.11) v1(77.39,124.32) v1(77.51,129.52) v1(77.51,128.25) v1(77.5,119.77) v1(77.49,71.69) v1(77.58,151.5) v1(77.61,150.48) v1(77.59,105.58) v1(78.33,101.11) v1(78.35,59.81) v1(78.35,58.54) v1(78.35,57.27) v1(78.35,56) v1(78.28,50.81) v1(78.28,49.54) v1(78.39,70.33) v1(78.39,69.06) v1(78.7,136.26) v1(78.67,105.62) v1(78.85,151.5) v1(78.76,71.69) v1(78.88,150.48) v1(78.96,122.82) v1(79.29,137.34) v1(79.29,124.93) v1(79.6,101.11) v1(79.62,59.81) v1(79.62,58.54) v1(79.62,57.27) v1(79.62,56) v1(79.55,50.81) v1(79.55,49.54) v1(79.92,105.08) v1(79.89,35.54) v1(80.03,71.69) v1(80.01,70.51) v1(80.12,151.5) v1(80.15,150.48) v1(80.69,137.36) v1(80.75,45.06) v1(80.82,50.81) v1(80.82,49.54) v1(80.77,42.66) v1(80.87,101.11) v1(80.89,59.81) v1(80.89,58.54) v1(80.89,57.27) v1(80.89,56) v1(81.15,122.79) v1(81.13,105.07) v1(81.3,71.69) v1(81.28,70.51) v1(81.39,151.5) v1(81.42,150.48) v1(81.44,29.82) v1(81.44,28.57) v1(81.41,27.55) v1(82.01,137.41) v1(82.02,45.06) v1(82.04,42.66) v1(82.14,101.11) v1(82.2,50.79) v1(82.2,49.52) v1(82.33,124.92) v1(82.32,105.08) v1(82.42,122.79) v1(82.5,38.35) v1(82.46,27.19) v1(82.57,71.69) v1(82.55,70.51) v1(82.66,151.5) v1(82.69,150.48) v1(82.67,28.57) v1(82.82,136.32) v1(82.77,29.79) v1(83.29,45.06) v1(83.31,42.66) v1(83.41,101.11) v1(83.47,50.79) v1(83.47,49.52) v1(83.56,105.08) v1(83.69,122.79) v1(83.84,71.69) v1(83.82,70.51) v1(83.79,27.48) v1(83.93,151.5) v1(83.96,150.48) v1(83.98,29.79) v1(83.99,28.64) v1(84.48,38.18) v1(84.68,101.11) v1(84.74,50.79) v1(84.74,49.52) v1(84.76,105.05) v1(84.96,122.79) v1(85.11,71.69) v1(85.09,70.51) v1(85.2,151.5) v1(85.23,150.48) v1(85.32,120.74) v1(85.89,113.18) v1(85.9,105.05) v1(85.95,101.11) v1(86.19,50.74) v1(86.19,49.47) v1(86.38,71.69) v1(86.36,70.51) v1(86.47,151.5) v1(86.5,150.48) v1(86.59,120.74) v1(87.07,136.39) v1(87.08,113.15) v1(87.12,105.05) v1(87.21,118.73) v1(87.22,101.11) v1(87.46,50.74) v1(87.46,49.47) v1(87.63,70.51) v1(87.74,151.5) v1(87.65,71.69) v1(87.73,45.1) v1(87.77,150.48) v1(88.23,136.39) v1(88.29,124.94) v1(88.28,113.16) v1(88.34,105.05) v1(88.53,137.34) v1(88.48,118.73) v1(88.49,101.11) v1(88.73,50.74) v1(88.73,49.47) v1(88.78,36.09) v1(88.92,71.69) v1(88.9,70.51) v1(89.01,151.5) v1(89.04,150.48) v1(89.43,38.9) v1(89.55,137.38) v1(89.5,113.16) v1(89.53,105.04) v1(89.76,101.11) v1(89.77,51.99) v1(89.77,50.72) v1(89.77,49.45) v1(89.94,26.89) v1(89.86,24.94) v1(90.19,71.69) v1(90.17,70.51) v1(90.28,151.5) v1(90.31,150.48) v1(90.69,113.19) v1(90.76,105.05) v1(91.03,101.11) v1(91.04,51.99) v1(91.04,50.72) v1(91.04,49.45) v1(91.01,29.72) v1(91.05,120.71) v1(91.16,124.9) v1(91.44,70.51) v1(91.55,151.5) v1(91.46,71.69) v1(91.49,32.06) v1(91.58,150.48) v1(91.74,56.26) v1(91.99,64.09) v1(91.98,59.55) v1(92.3,101.11) v1(92.73,71.69) v1(92.71,70.51) v1(92.82,151.5) v1(92.83,120.73) v1(92.81,67.67) v1(92.85,150.48) v1(93.21,64.09) v1(93.33,56.27) v1(93.57,101.11) v1(93.63,59.56) v1(93.72,67.65) v1(94,71.69) v1(93.98,70.51) v1(94.09,151.5) v1(94.12,150.48) v1(94.72,105.08) v1(94.78,113.23) v1(94.84,101.11) v1(95.27,71.69) v1(95.25,70.51) v1(95.36,151.5) v1(95.39,150.48) v1(95.91,124.16) v1(95.92,113.14) v1(96.04,129.31) v1(96.04,128.04) v1(95.96,105.06) v1(96.11,101.11) v1(96.54,71.69) v1(96.52,70.51) v1(96.55,56.34) v1(96.63,151.5) v1(96.55,55.73) v1(96.66,150.48) v1(96.98,67.65) v1(97.03,66.78) v1(97.1,113.14) v1(97.18,124.16) v1(97.16,105.06) v1(97.31,129.31) v1(97.31,128.04) v1(97.38,101.11) v1(97.81,71.69) v1(97.79,70.51) v1(97.9,151.5) v1(97.92,38.76) v1(98.33,113.14) v1(98.37,124.63) v1(98.37,123.36) v1(98.37,122.09) v1(98.36,105.07) v1(98.58,129.31) v1(98.58,128.04) v1(98.65,101.11) v1(99.08,71.69) v1(99.06,70.51) v1(99.17,151.5) v1(99.19,38.76) v1(99.51,113.14) v1(99.64,124.63) v1(99.64,123.36) v1(99.64,122.09) v1(99.57,105.08) v1(99.72,58.24) v1(99.85,129.31) v1(99.85,128.04) v1(99.92,101.11) v1(100.23,43.05) v1(100.33,70.51) v1(100.34,45.58) v1(100.44,151.5) v1(100.35,71.69) v1(100.46,38.76) v1(100.52,29.23) v1(100.52,28.2) v1(101.19,101.11) v1(101.43,27.16) v1(101.5,43.05) v1(101.62,71.69) v1(101.61,45.58) v1(101.71,151.5) v1(101.73,150.32) v1(101.71,149.13) v1(101.72,29.26) v1(101.73,28.17) v1(101.94,105.08) v1(102.46,101.11) v1(102.57,136.21) v1(102.77,43.05) v1(102.79,27.08) v1(102.89,71.69) v1(102.88,45.58) v1(102.98,151.5) v1(103,150.32) v1(102.98,149.13) v1(103.06,29.22) v1(103.07,28.19) v1(103.16,105.06) v1(103.33,137.71) v1(103.29,35.15) v1(103.8,38.01) v1(104.25,151.5) v1(104.25,149.13) v1(104.18,99.75) v1(104.18,98.48) v1(104.18,97.21) v1(104.18,95.94) v1(104.18,94.67) v1(104.18,93.4) v1(104.18,92.13) v1(104.18,90.86) v1(104.18,89.59) v1(104.18,88.32) v1(104.18,87.05) v1(104.18,85.78) v1(104.18,84.51) v1(104.18,83.24) v1(104.18,81.97) v1(104.18,80.7) v1(104.18,79.43) v1(104.18,78.16) v1(104.18,76.89) v1(104.18,75.62) v1(104.18,74.35) v1(104.18,73.08) v1(104.27,150.32) v1(104.35,105.07) v1(104.35,137.74) v1(104.79,120.64) v1(104.85,118.76) v1(105.52,151.5) v1(105.54,150.32) v1(105.52,149.13) v1(105.53,35) v1(105.61,137.71) v1(105.57,105.08) v1(105.6,46.14) v1(105.6,44.87) v1(105.6,43.6) v1(105.73,120.68) v1(105.66,51.99) v1(105.66,50.72) v1(105.66,49.45) v1(106.73,136.5) v1(106.79,151.5) v1(106.81,150.32) v1(106.79,149.13) v1(106.77,105.08) v1(106.93,51.99) v1(106.93,50.72) v1(106.93,49.45) v1(107.25,65.76) v1(107.51,120.66) v1(107.51,37.47) v1(107.61,20.97) v1(108.06,151.5) v1(108.16,118.52) v1(108.6,150.45) v1(108.6,147.61) v1(108.58,105.32) v1(108.68,21) v1(109.06,148.9) v1(109.33,151.5) v1(109.55,118.47) v1(109.83,20.45) v1(110.02,79.83) v1(110.23,150.39) v1(110.23,147.55) v1(110.24,67.99) v1(110.33,148.9) v1(110.25,75.79) v1(110.28,69.81) v1(110.42,74.74) v1(110.38,70.71) v1(110.6,151.5) v1(110.59,120.25) v1(110.59,118.98) v1(110.71,77.07) v1(111.38,31.78) v1(111.6,148.9) v1(111.87,151.5) v1(111.88,150.37) v1(111.88,147.53) v1(111.86,120.25) v1(111.86,118.98) v1(112.04,123.17) v1(112.13,105.23) v1(112.38,136.4) v1(112.74,19.73) v1(112.87,148.9) v1(112.89,29.05) v1(113.14,151.5) v1(113.13,120.25) v1(113.13,118.98) v1(113.5,150.35) v1(113.5,147.52) v1(113.53,136.45) v1(113.81,19.77) v1(113.87,123.14) v1(114.14,148.9) v1(114.41,151.5) v1(114.4,137.59) v1(114.53,23.35) v1(114.56,120.25) v1(114.56,118.98) v1(114.86,105.37) v1(115.18,124.98) v1(115.2,28.81) v1(115.48,137.59) v1(115.68,151.5) v1(115.83,120.25) v1(115.83,118.98) v1(115.91,18.69) v1(116.27,28.84) v1(116.49,45.87) v1(116.49,44.6) v1(116.49,43.33) v1(116.95,151.5) v1(116.98,18.72) v1(117.1,120.25) v1(117.1,118.98) v1(117.44,124.99) v1(118.11,150.54) v1(118.22,151.5) v1(118.29,78.05) v1(118.29,28.84) v1(118.26,22.68) v1(118.26,21.41) v1(118.26,20.14) v1(118.26,18.87) v1(118.26,17.6) v1(118.75,120.27) v1(118.75,119) v1(118.8,129.44) v1(118.8,128.17) v1(118.85,122.95) v1(118.85,121.68) v1(119.4,79.15) v1(119.4,75.73) v1(119.36,28.87) v1(119.49,151.5) v1(119.49,77.49) v1(119.75,150.48) v1(120.02,120.27) v1(120.02,119) v1(120.07,129.44) v1(120.07,128.17) v1(120.12,122.95) v1(120.12,121.68) v1(120.06,24.14) v1(120.18,148.55) v1(120.25,21.85) v1(120.25,20.58) v1(120.25,19.31) v1(120.25,18.04) v1(120.25,16.77) v1(120.76,151.5) v1(120.84,77.18) v1(120.88,52.27) v1(120.88,51) v1(120.88,49.73) v1(121.34,129.44) v1(121.34,128.17) v1(121.29,120.27) v1(121.29,119) v1(121.4,150.45) v1(121.39,122.95) v1(121.39,121.68) v1(121.45,148.55) v1(122.03,151.5) v1(122.15,52.27) v1(122.15,51) v1(122.15,49.73) v1(122.62,25.73) v1(122.62,24.46) v1(122.62,23.19) v1(122.62,21.92) v1(122.62,20.65) v1(122.62,19.38) v1(122.62,18.11) v1(122.62,16.84) v1(122.62,15.57) v1(122.62,14.3) v1(122.72,148.55) v1(122.71,27.11) v1(123.01,150.44) v1(123.3,151.5) v1(123.41,36.98) v1(123.41,35.71) v1(123.41,34.44) v1(123.41,33.17) v1(123.41,31.9) v1(123.49,38.35) v1(123.99,148.55) v1(124.57,151.5) v1(124.97,51.88) v1(124.97,50.61) v1(124.97,49.34) v1(124.97,48.07) v1(124.97,46.8) v1(125.25,27.11) v1(125.16,25.73) v1(125.16,24.46) v1(125.16,23.19) v1(125.16,21.92) v1(125.16,20.65) v1(125.16,19.38) v1(125.16,18.11) v1(125.16,16.84) v1(125.16,15.57) v1(125.16,14.3) v1(125.26,148.55) v1(125.84,151.5) v1(125.95,36.98) v1(125.95,35.71) v1(125.95,34.44) v1(125.95,33.17) v1(125.95,31.9) v1(126.03,38.35) v1(126.66,136.41) v1(126.92,148.93) v1(127.01,51.86) v1(127.01,50.59) v1(127.01,49.32) v1(127.01,48.05) v1(127.01,46.78) v1(127.11,151.5) v1(127.11,150.49) v1(127.16,12.61) v1(127.36,137.6) v1(127.66,124.89) v1(127.75,24.18) v1(127.75,22.85) v1(127.7,21.3) v1(127.7,19.97) v1(127.66,18.38) v1(127.66,17.05) v1(127.74,15.28) v1(127.74,13.95) v1(127.79,27.11) v1(127.79,25.78) v1(128.19,148.93) v1(128.38,151.5) v1(128.5,137.62) v1(128.53,35.43) v1(128.53,34.1) v1(128.49,32.55) v1(128.57,38.35) v1(128.57,37.02) v1(128.74,150.43) v1(129.46,148.93) v1(129.55,51.86) v1(129.55,50.59) v1(129.55,49.32) v1(129.55,48.05) v1(129.55,46.78) v1(129.65,151.5) v1(129.79,137.66) v1(129.92,17.49) v1(130.14,27.4) v1(130.14,15.28) v1(130.14,13.95) v1(130.39,150.41) v1(130.57,124.87) v1(130.73,148.93) v1(130.92,151.5) v1(131.14,136.56) v1(131.34,21.81) v1(131.95,147.57) v1(132,150.4) v1(132,148.93) v1(132.19,151.5) v1(132.22,51.84) v1(132.22,50.57) v1(132.22,49.3) v1(132.22,48.03) v1(132.22,46.76) v1(132.5,123.07) v1(132.55,121.19) v1(132.73,43.17) v1(132.74,40.5) v1(132.87,88.03) v1(132.88,86.18) v1(132.9,84.29) v1(133.39,151.5) v1(133.58,147.51) v1(133.74,86.18) v1(133.77,88.04) v1(133.78,84.27) v1(134.41,148.95) v1(134.43,51.97) v1(134.43,50.7) v1(134.43,49.43) v1(134.43,48.16) v1(134.43,46.89) v1(134.64,88.04) v1(134.63,86.18) v1(134.66,151.5) v1(134.65,84.28) v1(135.23,147.49) v1(135.49,150.41) v1(135.68,148.95) v1(135.93,151.5) v1(136.36,124.87) v1(136.85,147.47) v1(136.95,148.95) v1(136.94,136.35) v1(136.97,51.97) v1(136.97,50.7) v1(136.97,49.43) v1(136.97,48.16) v1(136.97,46.89) v1(137.12,150.35) v1(137.2,151.5) v1(137.77,145.37) v1(137.77,144.1) v1(137.77,142.83) v1(137.77,141.56) v1(137.77,140.29) v1(137.77,139.02) v1(137.79,137.4) v1(138.22,148.95) v1(138.47,151.5) v1(138.77,150.32) v1(139.04,145.37) v1(139.04,144.1) v1(139.04,142.83) v1(139.04,141.56) v1(139.04,140.29) v1(139.04,139.02) v1(139.09,137.44) v1(139.07,27.37) v1(139.34,124.83) v1(139.45,136.59) v1(139.37,48.95) v1(139.37,46.77) v1(139.49,148.95) v1(139.74,151.5) v1(139.72,85.97) v1(139.77,88.91) v1(139.79,87.54) v1(139.98,95.17) v1(140.06,60.9) v1(140.06,58.72) v1(140.17,20.29) v1(140.31,145.37) v1(140.31,144.1) v1(140.31,142.83) v1(140.31,141.56) v1(140.31,140.29) v1(140.31,139.02) v1(140.38,150.31) v1(140.64,48.95) v1(140.64,46.77) v1(140.82,88.93) v1(140.83,87.47) v1(140.77,85.91) v1(141.01,151.5) v1(141.06,21.58) v1(141.2,31.67) v1(141.16,18.4) v1(141.16,15.86) v1(141.33,60.9) v1(141.33,58.72) v1(141.33,34.82) v1(141.63,71) v1(141.56,26.76) v1(141.57,24.38) v1(141.91,48.95) v1(141.91,46.77) v1(142.15,96.41) v1(142.28,151.5) v1(142.25,39.67) v1(142.33,18.37) v1(142.33,15.83) v1(142.47,31.67) v1(142.6,34.82) v1(142.59,21.56) v1(142.83,26.76) v1(142.86,60.86) v1(142.86,58.67) v1(143.55,151.5) v1(143.65,148.88) v1(143.6,24.07) v1(143.55,18.52) v1(143.55,15.98) v1(143.74,31.67) v1(143.82,150.41) v1(143.87,34.82) v1(144.13,60.86) v1(144.13,58.67) v1(144.1,26.76) v1(144.13,21.49) v1(144.29,39.67) v1(144.82,151.5) v1(144.82,18.52) v1(144.82,15.98) v1(145.01,31.67) v1(145.14,34.82) v1(145.28,148.82) v1(145.37,26.76) v1(145.41,23.9) v1(145.46,150.35) v1(145.7,21.43) v1(146.09,151.5) v1(146.09,18.52) v1(146.09,15.98) v1(146.32,39.67) v1(146.28,31.67) v1(146.41,34.82) v1(146.64,26.76) v1(146.67,85.15) v1(146.68,23.9) v1(146.93,148.8) v1(147.1,150.32) v1(147.06,145.28) v1(147.06,144.01) v1(147.06,142.74) v1(147.06,141.47) v1(147.06,140.2) v1(147.06,138.93) v1(147.24,15.9) v1(147.36,151.5) v1(147.55,31.67) v1(147.68,63.59) v1(147.68,61.41) v1(147.68,34.82) v1(147.91,26.76) v1(148.04,136.52) v1(147.95,23.9) v1(148.33,145.28) v1(148.33,144.01) v1(148.33,142.74) v1(148.33,141.47) v1(148.33,140.2) v1(148.33,138.93) v1(148.35,39.67) v1(148.41,15.9) v1(148.55,148.78) v1(148.47,128.84) v1(148.49,100.29) v1(148.63,151.5) v1(148.72,150.31) v1(148.82,31.67) v1(148.95,63.59) v1(148.95,61.41) v1(148.95,34.82) v1(149.09,126.39) v1(149.12,85.11) v1(149.18,26.76) v1(149.22,23.9) v1(149.6,145.28) v1(149.6,144.01) v1(149.6,142.74) v1(149.6,141.47) v1(149.6,140.2) v1(149.6,138.93) v1(149.66,15.78) v1(149.9,151.5) v1(150.09,31.67) v1(150.24,100.31) v1(150.22,34.82) v1(150.38,39.67) v1(150.45,26.76) v1(150.49,23.9) v1(150.56,128.45) v1(150.93,15.78) v1(151.14,95.4) v1(151.17,151.5) v1(151.76,23.9) v1(151.98,44.38) v1(152.2,15.78) v1(152.44,151.5) v1(152.41,39.67) v1(152.53,109.93) v1(152.72,112.55) v1(152.79,85.02) v1(152.81,26.72) v1(153.03,23.9) v1(153.71,151.5) v1(154.01,44.38) v1(154.08,26.72) v1(154.15,23.72) v1(154.15,21.18) v1(154.15,18.64) v1(154.15,16.1) v1(154.27,109.8) v1(154.32,107.75) v1(154.35,85.2) v1(154.45,39.67) v1(154.65,150.58) v1(154.56,149.01) v1(154.98,151.5) v1(155.35,26.72) v1(155.42,23.72) v1(155.42,21.18) v1(155.42,18.64) v1(155.42,16.1) v1(156.05,44.38) v1(156.15,84.96) v1(156.25,151.5) v1(156.19,148.95) v1(156.28,150.52) v1(156.62,26.72) v1(156.69,23.72) v1(156.69,21.18) v1(156.69,18.64) v1(156.69,16.1) v1(157.52,151.5) v1(157.84,148.93) v1(157.93,150.5) v1(157.89,26.72) v1(157.95,23.74) v1(157.96,18.8) v1(157.96,16.4) v1(157.96,13.86) v1(158.08,44.38) v1(158.19,21.17) v1(158.79,151.5) v1(159.07,110.41) v1(159.16,26.72) v1(159.23,18.8) v1(159.23,16.4) v1(159.23,13.86) v1(159.31,109.21) v1(159.28,23.65) v1(159.54,150.48) v1(159.46,148.91) v1(159.55,34.68) v1(159.5,31.49) v1(159.72,53.87) v1(159.69,21.53) v1(159.81,49.93) v1(159.93,109.93) v1(159.91,78.25) v1(160.02,85.23) v1(160.06,151.5) v1(160.11,44.38) v1(160.43,26.72) v1(160.5,110.44) v1(160.52,109.07) v1(160.5,18.8) v1(160.5,16.4) v1(160.5,13.86) v1(160.58,70.26) v1(160.58,68.22) v1(160.58,66.19) v1(160.58,64.16) v1(160.58,62.13) v1(160.75,150.01) v1(160.82,34.68) v1(160.77,31.49) v1(160.78,23.74) v1(161.01,148.71) v1(160.99,53.87) v1(161.08,49.93) v1(161.33,151.5) v1(161.26,22.11) v1(161.7,26.72) v1(162.02,150.01) v1(162.04,31.49) v1(162.14,44.38) v1(162.09,34.68) v1(162.28,148.71) v1(162.26,53.87) v1(162.35,49.93) v1(162.6,151.5) v1(162.8,61.85) v1(162.91,66.4) v1(162.91,63.86) v1(162.97,87.98) v1(162.96,74.3) v1(162.96,71.76) v1(162.96,69.22) v1(163.16,123.3) v1(163.22,14.44) v1(163.22,13.17) v1(163.22,11.9) v1(163.29,150.01) v1(163.31,31.49) v1(163.36,34.68) v1(163.53,53.87) v1(163.55,148.71) v1(163.62,86) v1(163.62,49.93) v1(163.87,151.5) v1(164.17,44.38) v1(164.43,123.3) v1(164.43,85.39) v1(164.56,150.01) v1(164.63,34.68) v1(164.58,31.49) v1(164.82,148.71) v1(164.8,53.87) v1(164.89,49.93) v1(165.34,61.85) v1(165.36,151.47) v1(165.4,85.91) v1(165.5,74.3) v1(165.5,71.76) v1(165.5,69.22) v1(165.45,66.4) v1(165.45,63.86) v1(165.7,123.3) v1(165.9,34.68) v1(165.85,31.49) v1(166.07,53.87) v1(166.16,49.93) v1(166.49,85.45) v1(166.63,151.47) v1(166.97,123.3) v1(167.12,61.8) v1(167.12,31.49) v1(167.23,66.35) v1(167.23,63.81) v1(167.17,34.68) v1(167.28,95.79) v1(167.3,94.63) v1(167.27,74.25) v1(167.27,71.71) v1(167.27,69.17) v1(167.34,53.87) v1(167.43,49.93) v1(167.9,151.47) v1(167.95,150.37) v1(168.23,148.84) v1(168.24,123.3) v1(168.38,95.79) v1(168.4,94.63) v1(168.44,34.68) v1(168.39,31.49) v1(168.61,53.87) v1(168.7,49.93) v1(169.17,151.47) v1(169.22,150.37) v1(169.5,148.84) v1(169.51,123.3) v1(169.5,95.81) v1(169.49,94.63) v1(169.54,22.98) v1(169.66,61.8) v1(169.81,74.25) v1(169.81,71.71) v1(169.81,69.17) v1(169.77,66.35) v1(169.77,63.81) v1(170.44,151.47) v1(170.49,150.37) v1(170.65,15.96) v1(170.65,14.63) v1(170.73,95.83) v1(170.75,94.67) v1(170.69,18.84) v1(170.69,17.51) v1(170.77,148.84) v1(170.8,141.51) v1(170.89,143.08) v1(171.16,21) v1(171.71,151.47) v1(171.76,150.37) v1(171.76,30.88) v1(171.95,37.18) v1(172.04,148.84) v1(171.97,100.72) v1(172.42,141.49) v1(172.51,143.06) v1(172.64,150.35) v1(172.92,151.54) v1(172.94,15.94) v1(172.94,14.61) v1(172.99,18.82) v1(172.99,17.49) v1(173.13,148.65) v1(173.15,20.82) v1(174.01,43.2) v1(174.12,150.4) v1(174.19,151.54) v1(174.21,39.2) v1(175.03,66.09) v1(175.03,63.55) v1(175.08,73.99) v1(175.08,71.45) v1(175.08,68.91) v1(175.41,150.4) v1(175.52,151.47) v1(175.48,39.2) v1(175.53,18.82) v1(175.53,17.49) v1(175.48,15.94) v1(175.48,14.61) v1(175.55,20.52) v1(175.69,36.55) v1(175.69,34.52) v1(175.69,32.48) v1(175.69,30.45) v1(175.69,28.42) v1(175.69,26.39) v1(175.69,24.36) v1(175.84,148.78) v1(176.04,43.2) v1(176.33,150.48) v1(176.75,39.2) v1(177.41,50.31) v1(177.62,73.99) v1(177.62,71.45) v1(177.62,68.91) v1(177.57,66.09) v1(177.57,63.55) v1(178.02,39.2) v1(178.02,15.94) v1(178.02,14.61) v1(178.07,18.82) v1(178.07,17.49) v1(178.75,13.51) v1(179.02,43.18) v1(179.29,39.2) v1(179.36,151.4) v1(179.38,149.62) v1(179.63,145.83) v1(179.56,94.58) v1(179.62,91.63) v1(179.75,81.28) v1(180.08,50.83) v1(180.13,15.43) v1(180.35,151.42) v1(180.33,131.79) v1(180.36,149.63) v1(180.56,39.2) v1(180.76,76.76) v1(180.84,13.24) v1(180.97,99.27) v1(181.24,145.82) v1(181.3,102.86) v1(181.54,132.32) v1(181.49,84.34) v1(181.61,85.9) v1(181.78,81.69) v1(181.78,43.22) v1(181.83,39.2) v1(182.27,120.64) v1(182.32,90.76) v1(182.3,16.54) v1(182.42,85.19) v1(182.48,123.25) v1(182.47,14.74) v1(182.45,13.57) v1(183.02,130.98) v1(183.1,39.2) v1(183.21,85.98) v1(183.25,84.33) v1(183.29,145.87) v1(183.38,121.64) v1(183.48,119.27) v1(183.52,81.4) v1(183.55,131.55) v1(183.74,14.74) v1(183.72,13.57) v1(183.81,43.22) v1(183.99,56.24) v1(184.35,116.83) v1(184.35,115.56) v1(184.35,114.29) v1(184.42,16.48) v1(184.53,151.52) v1(184.54,149.73) v1(184.52,145.73) v1(184.56,122.78) v1(184.56,121.51) v1(184.56,120.24) v1(184.85,90.21) v1(185.01,14.74) v1(184.99,13.57) v1(185.51,151.53) v1(185.53,149.75) v1(185.62,116.83) v1(185.62,115.56) v1(185.62,114.29) v1(185.83,122.78) v1(185.83,121.51) v1(185.83,120.24) v1(185.85,86.87) v1(185.82,33.45) v1(186.01,66.75) v1(186.21,140.55) v1(186.3,142.12) v1(186.28,14.74) v1(186.26,13.57) v1(186.77,16.48) v1(186.89,116.83) v1(186.89,115.56) v1(186.89,114.29) v1(187.1,122.78) v1(187.1,121.51) v1(187.1,120.24) v1(187.18,151.45) v1(187.2,149.66) v1(187.16,45.32) v1(187.43,72.49) v1(187.35,64.26) v1(187.63,92.82) v1(187.69,62.32) v1(187.83,140.53) v1(187.78,54.69) v1(187.77,14.34) v1(187.91,142.1) v1(188.02,1.03) v1(188.15,144.37) v1(188.09,3.57) v1(188.17,151.47) v1(188.18,149.68) v1(188.16,116.83) v1(188.16,115.56) v1(188.16,114.29) v1(188.23,87.91) v1(188.22,59.11) v1(188.37,122.78) v1(188.37,121.51) v1(188.37,120.24) v1(188.45,72.48) v1(188.45,54.7) v1(188.54,12.26) v1(188.54,10.99) v1(188.5,8.75) v1(188.5,7.48) v1(188.57,19.06) v1(188.57,17.79) v1(188.88,2.38) v1(189.07,136.07) v1(189.07,6.07) v1(189.42,144.37) v1(189.43,116.83) v1(189.43,115.56) v1(189.43,114.29) v1(189.64,122.78) v1(189.64,121.51) v1(189.64,120.24) v1(189.63,1.02) v1(189.81,19.03) v1(189.81,17.76) v1(189.82,3.97) v1(190.34,136.07) v1(190.48,31.57) v1(190.54,29.94) v1(190.54,28.91) v1(190.59,6.88) v1(190.69,144.37) v1(190.7,116.83) v1(190.7,115.56) v1(190.7,114.29) v1(190.81,138.81) v1(190.91,122.78) v1(190.91,121.51) v1(190.91,120.24) v1(191.04,2.47) v1(191.2,20.16) v1(191.23,3.8) v1(191.19,0.95) v1(191.3,5.34) v1(191.38,38.17) v1(191.51,31.57) v1(191.61,136.07) v1(191.6,19.3) v1(192.14,147.82) v1(192.08,146.18) v1(192.08,138.81) v1(192.09,29.88) v1(192.09,28.85) v1(192.18,151.08) v1(192.17,149.46) v1(192.77,7.08) v1(192.77,4.54) v1(192.87,19.3) v1(193.02,36.69) v1(193.3,91.38) v1(193.3,29.92) v1(193.3,28.82) v1(193.35,138.81) v1(193.4,80.1) v1(193.92,146.18) v1(193.9,47.33) v1(193.9,46.06) v1(193.9,44.79) v1(193.9,43.52) v1(193.9,42.25) v1(193.9,40.98) v1(194.01,151.08) v1(194,149.46) v1(193.98,147.82) v1(194.05,5.74) v1(194.11,144.29) v1(194.06,13.48) v1(194.62,35.65) v1(194.87,12.08) v1(195.21,15.43) v1(195.33,13.48) v1(195.31,7.08) v1(195.31,4.54) v1(195.75,131.91) v1(195.93,133.88) v1(196.04,135.72) v1(196.44,47.33) v1(196.44,46.06) v1(196.44,44.79) v1(196.44,43.52) v1(196.44,42.25) v1(196.44,40.98) v1(196.42,11.1) v1(196.79,5.78) v1(197.02,131.91) v1(197.2,133.88) v1(197.15,17.71) v1(197.31,135.72) v1(197.42,151.18) v1(197.4,149.19) v1(197.42,147.37) v1(197.39,145.61) v1(197.41,144.34) v1(197.66,15.37) v1(197.81,142.75) v1(197.83,141.6) v1(197.85,87.72) v1(197.85,67.4) v1(197.78,13.79) v1(197.88,140.19) v1(197.93,80.12) v1(198.05,97.88) v1(198.03,19.41) v1(198.1,62.28) v1(198.14,33.66) v1(198.16,7.07) v1(198.29,131.91) v1(198.42,17.71) v1(198.47,133.88) v1(198.58,135.72) v1(198.74,64.87) v1(198.98,47.33) v1(198.98,46.06) v1(198.98,44.79) v1(198.98,43.52) v1(198.98,42.25) v1(198.98,40.98) v1(199.35,149.3) v1(199.34,145.72) v1(199.3,19.41) v1(199.29,3.72) v1(199.37,147.48) v1(199.4,144.25) v1(199.45,142.71) v1(199.43,141.43) v1(199.44,21.13) v1(199.36,1.23) v1(199.46,151.29) v1(199.49,140.15) v1(200.41,18.4) v1(200.53,11.36) v1(200.48,10.05) v1(200.48,8.72) v1(200.5,3.14) v1(200.61,12.97) v1(200.71,24.47) v1(200.71,23.2) v1(200.71,21.13) v1(200.66,16.92) v1(200.69,5.37) v1(200.78,27.53) v1(201.03,138.02) v1(201.06,19.72) v1(201.23,151.18) v1(201.21,149.19) v1(201.23,147.37) v1(201.2,145.61) v1(201.27,6.86) v1(201.35,144.16) v1(201.37,140.15) v1(201.39,136.1) v1(201.39,134.83) v1(201.39,133.56) v1(201.39,132.29) v1(201.39,131.02) v1(201.39,129.75) v1(201.38,128.55) v1(201.38,127.28) v1(201.38,126.01) v1(201.38,124.74) v1(201.38,123.47) v1(201.38,122.2) v1(201.38,120.93) v1(201.38,119.66) v1(201.38,118.39) v1(201.38,117.12) v1(201.38,115.85) v1(201.38,114.58) v1(201.38,113.31) v1(201.38,112.04) v1(201.43,110.71) v1(201.43,109.44) v1(201.43,108.17) v1(201.43,106.9) v1(201.43,105.63) v1(201.43,104.36) v1(201.43,100.62) v1(201.43,99.35) v1(201.43,98.08) v1(201.43,96.81) v1(201.43,95.54) v1(201.43,94.27) v1(201.43,93) v1(201.43,91.73) v1(201.43,90.46) v1(201.43,89.19) v1(201.43,87.92) v1(201.43,86.65) v1(201.43,85.36) v1(201.43,84.09) v1(201.43,82.82) v1(201.43,81.55) v1(201.43,80.28) v1(201.43,79.01) v1(201.43,77.81) v1(201.43,76.54) v1(201.43,75.27) v1(201.43,74) v1(201.43,72.73) v1(201.43,71.46) v1(201.43,70.19) v1(201.43,68.92) v1(201.43,67.65) v1(201.43,66.38) v1(201.43,65.11) v1(201.43,63.84) v1(201.43,62.57) v1(201.43,61.3) v1(201.38,1.37) v1(201.46,142.67) v1(201.46,141.4) v1(201.47,59.97) v1(201.47,58.7) v1(201.47,57.43) v1(201.47,56.16) v1(201.47,54.89) v1(201.47,53.62) v1(201.47,52.42) v1(201.47,51.15) v1(201.47,49.88) v1(201.47,48.61) v1(201.47,47.34) v1(201.47,46.07) v1(201.47,44.8) v1(201.47,43.53) v1(201.47,42.26) v1(201.47,40.99) v1(201.47,39.72) v1(201.47,38.45) v1(201.47,37.18) v1(201.47,35.91) v1(202.36,32.75) v1(202.36,31.48) v1(202.36,30.21) v1(202.36,28.94) v1(202.36,27.67) v1(202.36,26.4) v1(202.36,25.13) v1(202.36,23.86) v1(202.36,22.59) v1(202.36,21.32) v1(202.36,20.05) v1(202.36,18.78) v1(202.36,17.51) v1(202.36,16.24) v1(202.36,14.97) v1(202.36,13.7) v1(202.36,12.43) v1(202.36,11.16) v1(202.36,9.89) v1(202.36,8.62) v1(203.1,151.18) v1(203.66,1.31) v1(203.86,143.55) v1(203.86,141.52) v1(203.86,139.49) v1(203.86,137.46) v1(203.86,135.42) v1(203.86,133.39) v1(203.86,131.36) v1(203.86,129.33) v1(203.86,127.3) v1(203.86,125.26) v1(203.86,123.23) v1(203.86,121.2) v1(203.86,119.17) v1(203.86,117.14) v1(203.86,115.1) v1(203.86,113.07) v1(203.86,111.04) v1(203.86,109.01) v1(203.86,106.98) v1(203.86,104.94) v1(203.86,102.91) v1(203.86,100.88) v1(203.86,98.85) v1(203.86,96.82) v1(203.86,94.78) v1(203.86,92.75) v1(203.86,90.72) v1(203.86,88.69) v1(203.86,86.66) v1(203.86,84.62) v1(203.86,82.59) v1(203.86,80.56) v1(203.86,78.53) v1(203.86,76.5) v1(203.86,74.46) v1(203.86,72.43) v1(203.86,70.4) v1(203.86,68.37) v1(203.86,66.34) v1(203.86,64.3) v1(203.86,62.27) v1(203.86,60.24) v1(203.86,58.21) v1(203.86,56.18) v1(203.86,54.14) v1(203.86,52.11) v1(203.86,50.08) v1(203.86,48.05) v1(203.86,46.02) v1(203.86,43.98) v1(203.86,41.95) v1(203.86,39.92) v1(203.86,37.89) v1(203.86,35.86) v1(203.86,33.82) v1(203.86,31.79) v1(203.86,29.76) v1(203.86,27.73) v1(203.86,25.7) v1(203.86,23.66) v1(203.86,21.63) v1(203.86,19.6) v1(203.86,17.57) v1(203.86,15.54) v1(203.86,13.5) v1(203.86,11.47) v1(203.86,9.44) v1(205.23,150.95) v1(205.89,143.55) v1(205.89,141.52) v1(205.89,139.49) v1(205.89,137.46) v1(205.89,135.42) v1(205.89,133.39) v1(205.89,131.36) v1(205.89,129.33) v1(205.89,127.3) v1(205.89,125.26) v1(205.89,123.23) v1(205.89,121.2) v1(205.89,119.17) v1(205.89,117.14) v1(205.89,115.1) v1(205.89,113.07) v1(205.89,111.04) v1(205.89,109.01) v1(205.89,106.98) v1(205.89,104.94) v1(205.89,102.91) v1(205.89,100.88) v1(205.89,98.85) v1(205.89,96.82) v1(205.89,94.78) v1(205.89,92.75) v1(205.89,90.72) v1(205.89,88.69) v1(205.89,86.66) v1(205.89,84.62) v1(205.89,82.59) v1(205.89,80.56) v1(205.89,78.53) v1(205.89,76.5) v1(205.89,74.46) v1(205.89,72.43) v1(205.89,70.4) v1(205.89,68.37) v1(205.89,66.34) v1(205.89,64.3) v1(205.89,62.27) v1(205.89,60.24) v1(205.89,58.21) v1(205.89,56.18) v1(205.89,54.14) v1(205.89,52.11) v1(205.89,50.08) v1(205.89,48.05) v1(205.89,46.02) v1(205.89,43.98) v1(205.89,41.95) v1(205.89,39.92) v1(205.89,37.89) v1(205.89,35.86) v1(205.89,33.82) v1(205.89,31.79) v1(205.89,29.76) v1(205.89,27.73) v1(205.89,25.7) v1(205.89,23.66) v1(205.89,21.63) v1(205.89,19.6) v1(205.89,17.57) v1(205.89,15.54) v1(205.89,13.5) v1(205.89,11.47) v1(205.89,9.44) v1(206.73,1.51) v1(206.94,150.35) v1(207.92,143.55) v1(207.92,141.52) v1(207.92,139.49) v1(207.92,137.46) v1(207.92,135.42) v1(207.92,133.39) v1(207.92,131.36) v1(207.92,129.33) v1(207.92,127.3) v1(207.92,125.26) v1(207.92,123.23) v1(207.92,121.2) v1(207.92,119.17) v1(207.92,117.14) v1(207.92,115.1) v1(207.92,113.07) v1(207.92,111.04) v1(207.92,109.01) v1(207.92,106.98) v1(207.92,104.94) v1(207.92,102.91) v1(207.92,100.88) v1(207.92,98.85) v1(207.92,96.82) v1(207.92,94.78) v1(207.92,92.75) v1(207.92,90.72) v1(207.92,88.69) v1(207.92,86.66) v1(207.92,84.62) v1(207.92,82.59) v1(207.92,80.56) v1(207.92,78.53) v1(207.92,76.5) v1(207.92,74.46) v1(207.92,72.43) v1(207.92,70.4) v1(207.92,68.37) v1(207.92,66.34) v1(207.92,64.3) v1(207.92,62.27) v1(207.92,60.24) v1(207.92,58.21) v1(207.92,56.18) v1(207.92,54.14) v1(207.92,52.11) v1(207.92,50.08) v1(207.92,48.05) v1(207.92,46.02) v1(207.92,43.98) v1(207.92,41.95) v1(207.92,39.92) v1(207.92,37.89) v1(207.92,35.86) v1(207.92,33.82) v1(207.92,31.79) v1(207.92,29.76) v1(207.92,27.73) v1(207.92,25.7) v1(207.92,23.66) v1(207.92,21.63) v1(207.92,19.6) v1(207.92,17.57) v1(207.92,15.54) v1(207.92,13.5) v1(207.92,11.47) v1(207.92,9.44) v1(208.33,148.89) v1(208.39,3.97) v1(208.47,7.09) v1(208.66,146.83) v1(208.71,145.06)
